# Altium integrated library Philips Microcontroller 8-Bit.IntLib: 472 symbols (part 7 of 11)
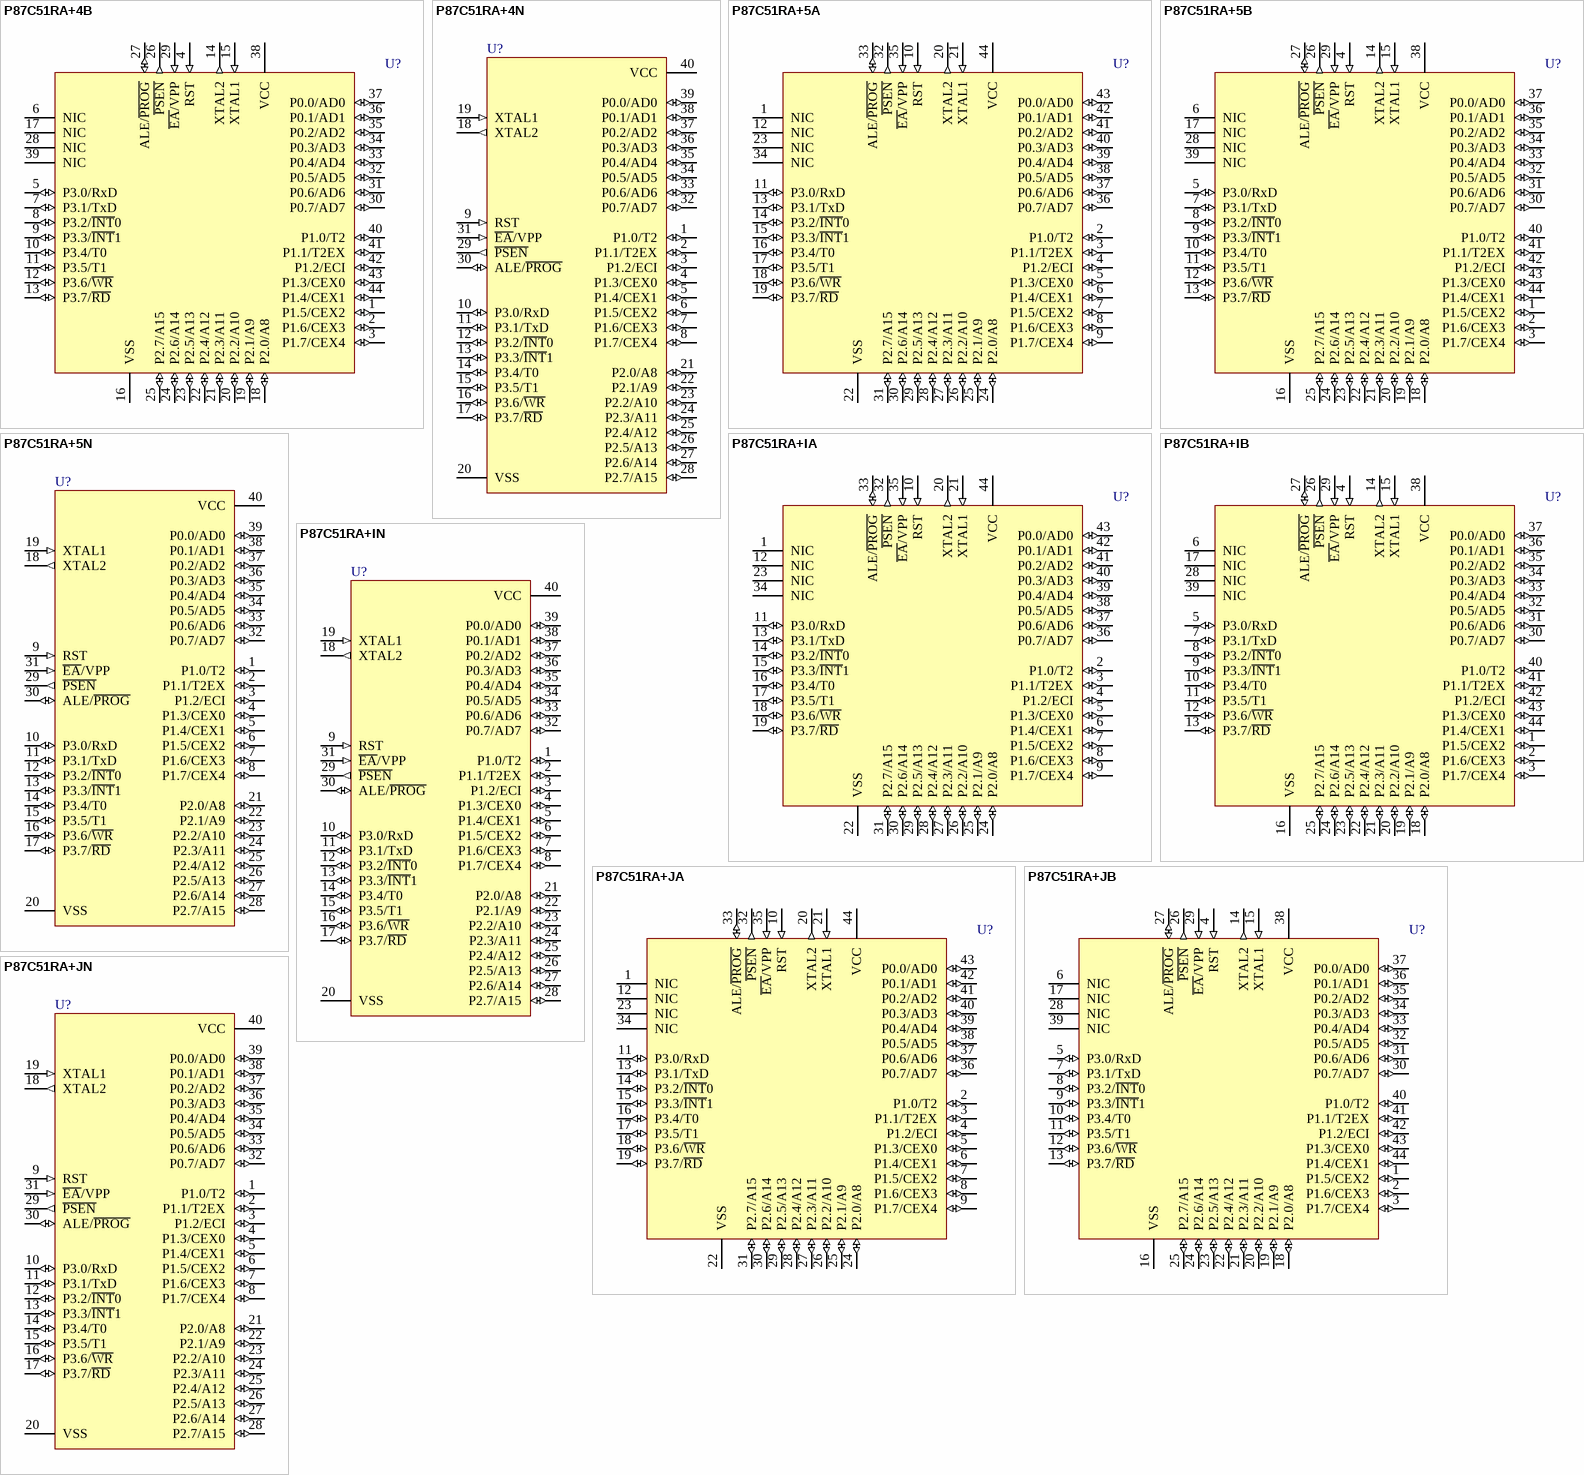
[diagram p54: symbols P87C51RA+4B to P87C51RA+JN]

## P87C51RA+5B
designator U?
80C51 8-Bit Microcontroller Family: 512 B RAM, 8 kB OTP, 2.7V-5.5V, Low Power, High Speed
footprint SOT307-2_N (QFP, 44-Leads, Body 10x10mm, Pitch 0.8mm, IPC Medium Density)
footprint SOT307-2_L (QFP, 44-Leads, Body 10x10mm, Pitch 0.8mm, IPC High Density)
footprint SOT307-2_M (QFP, 44-Leads, Body 10x10mm, Pitch 0.8mm, IPC Low Density)
pins: 1 P1.5/CEX2 (io), 2 P1.6/CEX3 (io), 3 P1.7/CEX4 (io), 4 RST (in), 5 P3.0/RxD (io), 6 NIC, 7 P3.1/TxD (io), 8 P3.2/~{INT}0 (io), 9 P3.3/~{INT}1 (io), 10 P3.4/T0 (io), 11 P3.5/T1 (io), 12 P3.6/~{WR} (io), 13 P3.7/~{RD} (io), 14 XTAL2 (out), 15 XTAL1 (in), 16 VSS (power), 17 NIC, 18 P2.0/A8 (io), 19 P2.1/A9 (io), 20 P2.2/A10 (io), 21 P2.3/A11 (io), 22 P2.4/A12 (io), 23 P2.5/A13 (io), 24 P2.6/A14 (io), 25 P2.7/A15 (io), 26 ~{PSEN} (out), 27 ALE/~{PROG} (io), 28 NIC, 29 ~{EA}/VPP (in), 30 P0.7/AD7 (io), 31 P0.6/AD6 (io), 32 P0.5/AD5 (io), 33 P0.4/AD4 (io), 34 P0.3/AD3 (io), 35 P0.2/AD2 (io), 36 P0.1/AD1 (io), 37 P0.0/AD0 (io), 38 VCC (power), 39 NIC, 40 P1.0/T2 (io), 41 P1.1/T2EX (io), 42 P1.2/ECI (io), 43 P1.3/CEX0 (io), 44 P1.4/CEX1 (io)

## P87C51RA+5N
designator U?
80C51 8-Bit Microcontroller Family: 512 B RAM, 8 kB OTP, 2.7V-5.5V, Low Power, High Speed
footprint SOT129-1 (DIP, Plastic; 40 Leads; Row Spacing 15.24 mm; Pitch 2.54 mm)
pins: 1 P1.0/T2 (io), 2 P1.1/T2EX (io), 3 P1.2/ECI (io), 4 P1.3/CEX0 (io), 5 P1.4/CEX1 (io), 6 P1.5/CEX2 (io), 7 P1.6/CEX3 (io), 8 P1.7/CEX4 (io), 9 RST (in), 10 P3.0/RxD (io), 11 P3.1/TxD (io), 12 P3.2/~{INT}0 (io), 13 P3.3/~{INT}1 (io), 14 P3.4/T0 (io), 15 P3.5/T1 (io), 16 P3.6/~{WR} (io), 17 P3.7/~{RD} (io), 18 XTAL2 (out), 19 XTAL1 (in), 20 VSS (power), 21 P2.0/A8 (io), 22 P2.1/A9 (io), 23 P2.2/A10 (io), 24 P2.3/A11 (io), 25 P2.4/A12 (io), 26 P2.5/A13 (io), 27 P2.6/A14 (io), 28 P2.7/A15 (io), 29 ~{PSEN} (out), 30 ALE/~{PROG} (io), 31 ~{EA}/VPP (in), 32 P0.7/AD7 (io), 33 P0.6/AD6 (io), 34 P0.5/AD5 (io), 35 P0.4/AD4 (io), 36 P0.3/AD3 (io), 37 P0.2/AD2 (io), 38 P0.1/AD1 (io), 39 P0.0/AD0 (io), 40 VCC (power)

## P87C51RA+IA
designator U?
80C51 8-Bit Microcontroller Family: 512 B RAM, 8 kB OTP, 5V, Low Power, High Speed
footprint SOT187-2_N (Leaded Chip Carrier, 44-Leads, Body 16.6x16.6mm, Pitch 1.27mm, IPC Medium Density)
footprint SOT187-2_L (Leaded Chip Carrier, 44-Leads, Body 16.6x16.6mm, Pitch 1.27mm, IPC High Density)
footprint SOT187-2_M (Leaded Chip Carrier, 44-Leads, Body 16.6x16.6mm, Pitch 1.27mm, IPC Low Density)
pins: 1 NIC, 2 P1.0/T2 (io), 3 P1.1/T2EX (io), 4 P1.2/ECI (io), 5 P1.3/CEX0 (io), 6 P1.4/CEX1 (io), 7 P1.5/CEX2 (io), 8 P1.6/CEX3 (io), 9 P1.7/CEX4 (io), 10 RST (in), 11 P3.0/RxD (io), 12 NIC, 13 P3.1/TxD (io), 14 P3.2/~{INT}0 (io), 15 P3.3/~{INT}1 (io), 16 P3.4/T0 (io), 17 P3.5/T1 (io), 18 P3.6/~{WR} (io), 19 P3.7/~{RD} (io), 20 XTAL2 (out), 21 XTAL1 (in), 22 VSS (power), 23 NIC, 24 P2.0/A8 (io), 25 P2.1/A9 (io), 26 P2.2/A10 (io), 27 P2.3/A11 (io), 28 P2.4/A12 (io), 29 P2.5/A13 (io), 30 P2.6/A14 (io), 31 P2.7/A15 (io), 32 ~{PSEN} (out), 33 ALE/~{PROG} (io), 34 NIC, 35 ~{EA}/VPP (in), 36 P0.7/AD7 (io), 37 P0.6/AD6 (io), 38 P0.5/AD5 (io), 39 P0.4/AD4 (io), 40 P0.3/AD3 (io), 41 P0.2/AD2 (io), 42 P0.1/AD1 (io), 43 P0.0/AD0 (io), 44 VCC (power)

## P87C51RA+IB
designator U?
80C51 8-Bit Microcontroller Family: 512 B RAM, 8 kB OTP, 5V, Low Power, High Speed
footprint SOT307-2_N (QFP, 44-Leads, Body 10x10mm, Pitch 0.8mm, IPC Medium Density)
footprint SOT307-2_L (QFP, 44-Leads, Body 10x10mm, Pitch 0.8mm, IPC High Density)
footprint SOT307-2_M (QFP, 44-Leads, Body 10x10mm, Pitch 0.8mm, IPC Low Density)
pins: 1 P1.5/CEX2 (io), 2 P1.6/CEX3 (io), 3 P1.7/CEX4 (io), 4 RST (in), 5 P3.0/RxD (io), 6 NIC, 7 P3.1/TxD (io), 8 P3.2/~{INT}0 (io), 9 P3.3/~{INT}1 (io), 10 P3.4/T0 (io), 11 P3.5/T1 (io), 12 P3.6/~{WR} (io), 13 P3.7/~{RD} (io), 14 XTAL2 (out), 15 XTAL1 (in), 16 VSS (power), 17 NIC, 18 P2.0/A8 (io), 19 P2.1/A9 (io), 20 P2.2/A10 (io), 21 P2.3/A11 (io), 22 P2.4/A12 (io), 23 P2.5/A13 (io), 24 P2.6/A14 (io), 25 P2.7/A15 (io), 26 ~{PSEN} (out), 27 ALE/~{PROG} (io), 28 NIC, 29 ~{EA}/VPP (in), 30 P0.7/AD7 (io), 31 P0.6/AD6 (io), 32 P0.5/AD5 (io), 33 P0.4/AD4 (io), 34 P0.3/AD3 (io), 35 P0.2/AD2 (io), 36 P0.1/AD1 (io), 37 P0.0/AD0 (io), 38 VCC (power), 39 NIC, 40 P1.0/T2 (io), 41 P1.1/T2EX (io), 42 P1.2/ECI (io), 43 P1.3/CEX0 (io), 44 P1.4/CEX1 (io)

## P87C51RA+IN
designator U?
80C51 8-Bit Microcontroller Family: 512 B RAM, 8 kB OTP, 5V, Low Power, High Speed
footprint SOT129-1 (DIP, Plastic; 40 Leads; Row Spacing 15.24 mm; Pitch 2.54 mm)
pins: 1 P1.0/T2 (io), 2 P1.1/T2EX (io), 3 P1.2/ECI (io), 4 P1.3/CEX0 (io), 5 P1.4/CEX1 (io), 6 P1.5/CEX2 (io), 7 P1.6/CEX3 (io), 8 P1.7/CEX4 (io), 9 RST (in), 10 P3.0/RxD (io), 11 P3.1/TxD (io), 12 P3.2/~{INT}0 (io), 13 P3.3/~{INT}1 (io), 14 P3.4/T0 (io), 15 P3.5/T1 (io), 16 P3.6/~{WR} (io), 17 P3.7/~{RD} (io), 18 XTAL2 (out), 19 XTAL1 (in), 20 VSS (power), 21 P2.0/A8 (io), 22 P2.1/A9 (io), 23 P2.2/A10 (io), 24 P2.3/A11 (io), 25 P2.4/A12 (io), 26 P2.5/A13 (io), 27 P2.6/A14 (io), 28 P2.7/A15 (io), 29 ~{PSEN} (out), 30 ALE/~{PROG} (io), 31 ~{EA}/VPP (in), 32 P0.7/AD7 (io), 33 P0.6/AD6 (io), 34 P0.5/AD5 (io), 35 P0.4/AD4 (io), 36 P0.3/AD3 (io), 37 P0.2/AD2 (io), 38 P0.1/AD1 (io), 39 P0.0/AD0 (io), 40 VCC (power)

## P87C51RA+JA
designator U?
80C51 8-Bit Microcontroller Family: 512 B RAM, 8 kB OTP, 5V, Low Power, High Speed
footprint SOT187-2_N (Leaded Chip Carrier, 44-Leads, Body 16.6x16.6mm, Pitch 1.27mm, IPC Medium Density)
footprint SOT187-2_L (Leaded Chip Carrier, 44-Leads, Body 16.6x16.6mm, Pitch 1.27mm, IPC High Density)
footprint SOT187-2_M (Leaded Chip Carrier, 44-Leads, Body 16.6x16.6mm, Pitch 1.27mm, IPC Low Density)
pins: 1 NIC, 2 P1.0/T2 (io), 3 P1.1/T2EX (io), 4 P1.2/ECI (io), 5 P1.3/CEX0 (io), 6 P1.4/CEX1 (io), 7 P1.5/CEX2 (io), 8 P1.6/CEX3 (io), 9 P1.7/CEX4 (io), 10 RST (in), 11 P3.0/RxD (io), 12 NIC, 13 P3.1/TxD (io), 14 P3.2/~{INT}0 (io), 15 P3.3/~{INT}1 (io), 16 P3.4/T0 (io), 17 P3.5/T1 (io), 18 P3.6/~{WR} (io), 19 P3.7/~{RD} (io), 20 XTAL2 (out), 21 XTAL1 (in), 22 VSS (power), 23 NIC, 24 P2.0/A8 (io), 25 P2.1/A9 (io), 26 P2.2/A10 (io), 27 P2.3/A11 (io), 28 P2.4/A12 (io), 29 P2.5/A13 (io), 30 P2.6/A14 (io), 31 P2.7/A15 (io), 32 ~{PSEN} (out), 33 ALE/~{PROG} (io), 34 NIC, 35 ~{EA}/VPP (in), 36 P0.7/AD7 (io), 37 P0.6/AD6 (io), 38 P0.5/AD5 (io), 39 P0.4/AD4 (io), 40 P0.3/AD3 (io), 41 P0.2/AD2 (io), 42 P0.1/AD1 (io), 43 P0.0/AD0 (io), 44 VCC (power)

## P87C51RA+JB
designator U?
80C51 8-Bit Microcontroller Family: 512 B RAM, 8 kB OTP, 5V, Low Power, High Speed
footprint SOT307-2_N (QFP, 44-Leads, Body 10x10mm, Pitch 0.8mm, IPC Medium Density)
footprint SOT307-2_L (QFP, 44-Leads, Body 10x10mm, Pitch 0.8mm, IPC High Density)
footprint SOT307-2_M (QFP, 44-Leads, Body 10x10mm, Pitch 0.8mm, IPC Low Density)
pins: 1 P1.5/CEX2 (io), 2 P1.6/CEX3 (io), 3 P1.7/CEX4 (io), 4 RST (in), 5 P3.0/RxD (io), 6 NIC, 7 P3.1/TxD (io), 8 P3.2/~{INT}0 (io), 9 P3.3/~{INT}1 (io), 10 P3.4/T0 (io), 11 P3.5/T1 (io), 12 P3.6/~{WR} (io), 13 P3.7/~{RD} (io), 14 XTAL2 (out), 15 XTAL1 (in), 16 VSS (power), 17 NIC, 18 P2.0/A8 (io), 19 P2.1/A9 (io), 20 P2.2/A10 (io), 21 P2.3/A11 (io), 22 P2.4/A12 (io), 23 P2.5/A13 (io), 24 P2.6/A14 (io), 25 P2.7/A15 (io), 26 ~{PSEN} (out), 27 ALE/~{PROG} (io), 28 NIC, 29 ~{EA}/VPP (in), 30 P0.7/AD7 (io), 31 P0.6/AD6 (io), 32 P0.5/AD5 (io), 33 P0.4/AD4 (io), 34 P0.3/AD3 (io), 35 P0.2/AD2 (io), 36 P0.1/AD1 (io), 37 P0.0/AD0 (io), 38 VCC (power), 39 NIC, 40 P1.0/T2 (io), 41 P1.1/T2EX (io), 42 P1.2/ECI (io), 43 P1.3/CEX0 (io), 44 P1.4/CEX1 (io)

## P87C51RA+JN
designator U?
80C51 8-Bit Microcontroller Family: 512 B RAM, 8 kB OTP, 5V, Low Power, High Speed
footprint SOT129-1 (DIP, Plastic; 40 Leads; Row Spacing 15.24 mm; Pitch 2.54 mm)
pins: 1 P1.0/T2 (io), 2 P1.1/T2EX (io), 3 P1.2/ECI (io), 4 P1.3/CEX0 (io), 5 P1.4/CEX1 (io), 6 P1.5/CEX2 (io), 7 P1.6/CEX3 (io), 8 P1.7/CEX4 (io), 9 RST (in), 10 P3.0/RxD (io), 11 P3.1/TxD (io), 12 P3.2/~{INT}0 (io), 13 P3.3/~{INT}1 (io), 14 P3.4/T0 (io), 15 P3.5/T1 (io), 16 P3.6/~{WR} (io), 17 P3.7/~{RD} (io), 18 XTAL2 (out), 19 XTAL1 (in), 20 VSS (power), 21 P2.0/A8 (io), 22 P2.1/A9 (io), 23 P2.2/A10 (io), 24 P2.3/A11 (io), 25 P2.4/A12 (io), 26 P2.5/A13 (io), 27 P2.6/A14 (io), 28 P2.7/A15 (io), 29 ~{PSEN} (out), 30 ALE/~{PROG} (io), 31 ~{EA}/VPP (in), 32 P0.7/AD7 (io), 33 P0.6/AD6 (io), 34 P0.5/AD5 (io), 35 P0.4/AD4 (io), 36 P0.3/AD3 (io), 37 P0.2/AD2 (io), 38 P0.1/AD1 (io), 39 P0.0/AD0 (io), 40 VCC (power)

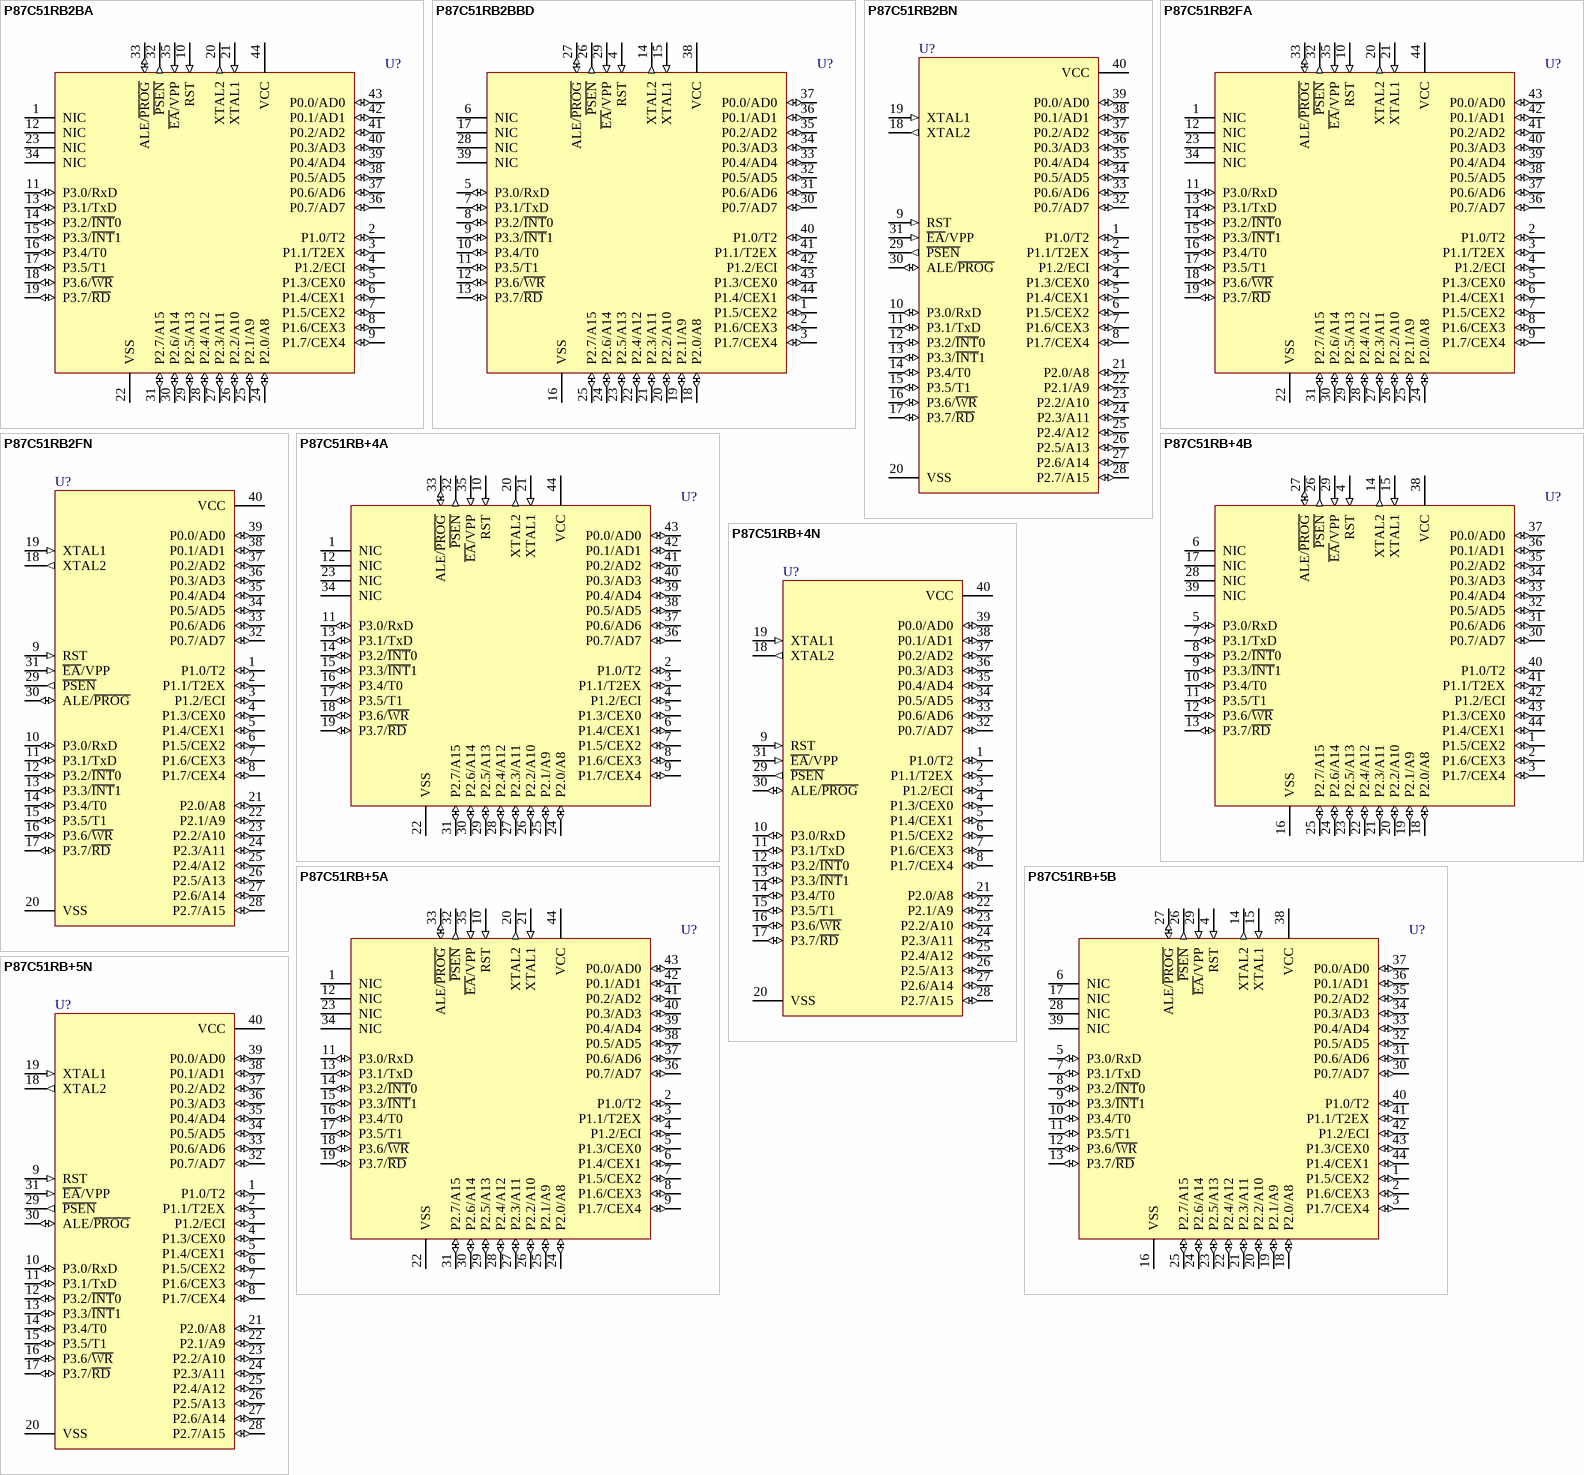
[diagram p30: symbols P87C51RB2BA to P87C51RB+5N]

## P87C51RB2BA
designator U?
80C51 8-Bit Microcontroller Family: 16 kB OTP with 512 B RAM, 2.7 to 5.5 V, Low Power, High Speed
footprint SOT187-2_N (Leaded Chip Carrier, 44-Leads, Body 16.6x16.6mm, Pitch 1.27mm, IPC Medium Density)
footprint SOT187-2_L (Leaded Chip Carrier, 44-Leads, Body 16.6x16.6mm, Pitch 1.27mm, IPC High Density)
footprint SOT187-2_M (Leaded Chip Carrier, 44-Leads, Body 16.6x16.6mm, Pitch 1.27mm, IPC Low Density)
pins: 1 NIC, 2 P1.0/T2 (io), 3 P1.1/T2EX (io), 4 P1.2/ECI (io), 5 P1.3/CEX0 (io), 6 P1.4/CEX1 (io), 7 P1.5/CEX2 (io), 8 P1.6/CEX3 (io), 9 P1.7/CEX4 (io), 10 RST (in), 11 P3.0/RxD (io), 12 NIC, 13 P3.1/TxD (io), 14 P3.2/~{INT}0 (io), 15 P3.3/~{INT}1 (io), 16 P3.4/T0 (io), 17 P3.5/T1 (io), 18 P3.6/~{WR} (io), 19 P3.7/~{RD} (io), 20 XTAL2 (out), 21 XTAL1 (in), 22 VSS (power), 23 NIC, 24 P2.0/A8 (io), 25 P2.1/A9 (io), 26 P2.2/A10 (io), 27 P2.3/A11 (io), 28 P2.4/A12 (io), 29 P2.5/A13 (io), 30 P2.6/A14 (io), 31 P2.7/A15 (io), 32 ~{PSEN} (out), 33 ALE/~{PROG} (io), 34 NIC, 35 ~{EA}/VPP (in), 36 P0.7/AD7 (io), 37 P0.6/AD6 (io), 38 P0.5/AD5 (io), 39 P0.4/AD4 (io), 40 P0.3/AD3 (io), 41 P0.2/AD2 (io), 42 P0.1/AD1 (io), 43 P0.0/AD0 (io), 44 VCC (power)

## P87C51RB2BBD
designator U?
80C51 8-Bit Microcontroller Family: 16 kB OTP with 512 B RAM, 2.7 to 5.5 V, Low Power, High Speed
footprint SOT389-1_N (Thin QFP, 44-Leads, Body 10x10mm, Pitch 0.8mm, IPC Medium Density)
footprint SOT389-1_L (Thin QFP, 44-Leads, Body 10x10mm, Pitch 0.8mm, IPC High Density)
footprint SOT389-1_M (Thin QFP, 44-Leads, Body 10x10mm, Pitch 0.8mm, IPC Low Density)
pins: 1 P1.5/CEX2 (io), 2 P1.6/CEX3 (io), 3 P1.7/CEX4 (io), 4 RST (in), 5 P3.0/RxD (io), 6 NIC, 7 P3.1/TxD (io), 8 P3.2/~{INT}0 (io), 9 P3.3/~{INT}1 (io), 10 P3.4/T0 (io), 11 P3.5/T1 (io), 12 P3.6/~{WR} (io), 13 P3.7/~{RD} (io), 14 XTAL2 (out), 15 XTAL1 (in), 16 VSS (power), 17 NIC, 18 P2.0/A8 (io), 19 P2.1/A9 (io), 20 P2.2/A10 (io), 21 P2.3/A11 (io), 22 P2.4/A12 (io), 23 P2.5/A13 (io), 24 P2.6/A14 (io), 25 P2.7/A15 (io), 26 ~{PSEN} (out), 27 ALE/~{PROG} (io), 28 NIC, 29 ~{EA}/VPP (in), 30 P0.7/AD7 (io), 31 P0.6/AD6 (io), 32 P0.5/AD5 (io), 33 P0.4/AD4 (io), 34 P0.3/AD3 (io), 35 P0.2/AD2 (io), 36 P0.1/AD1 (io), 37 P0.0/AD0 (io), 38 VCC (power), 39 NIC, 40 P1.0/T2 (io), 41 P1.1/T2EX (io), 42 P1.2/ECI (io), 43 P1.3/CEX0 (io), 44 P1.4/CEX1 (io)

## P87C51RB2BN
designator U?
80C51 8-Bit Microcontroller Family: 16 kB OTP with 512 B RAM, 2.7 to 5.5 V, Low Power, High Speed
footprint SOT129-1 (DIP, Plastic; 40 Leads; Row Spacing 15.24 mm; Pitch 2.54 mm)
pins: 1 P1.0/T2 (io), 2 P1.1/T2EX (io), 3 P1.2/ECI (io), 4 P1.3/CEX0 (io), 5 P1.4/CEX1 (io), 6 P1.5/CEX2 (io), 7 P1.6/CEX3 (io), 8 P1.7/CEX4 (io), 9 RST (in), 10 P3.0/RxD (io), 11 P3.1/TxD (io), 12 P3.2/~{INT}0 (io), 13 P3.3/~{INT}1 (io), 14 P3.4/T0 (io), 15 P3.5/T1 (io), 16 P3.6/~{WR} (io), 17 P3.7/~{RD} (io), 18 XTAL2 (out), 19 XTAL1 (in), 20 VSS (power), 21 P2.0/A8 (io), 22 P2.1/A9 (io), 23 P2.2/A10 (io), 24 P2.3/A11 (io), 25 P2.4/A12 (io), 26 P2.5/A13 (io), 27 P2.6/A14 (io), 28 P2.7/A15 (io), 29 ~{PSEN} (out), 30 ALE/~{PROG} (io), 31 ~{EA}/VPP (in), 32 P0.7/AD7 (io), 33 P0.6/AD6 (io), 34 P0.5/AD5 (io), 35 P0.4/AD4 (io), 36 P0.3/AD3 (io), 37 P0.2/AD2 (io), 38 P0.1/AD1 (io), 39 P0.0/AD0 (io), 40 VCC (power)

## P87C51RB2FA
designator U?
80C51 8-Bit Microcontroller Family: 16 kB OTP with 512 B RAM, 2.7 to 5.5 V, Low Power, High Speed
footprint SOT187-2_N (Leaded Chip Carrier, 44-Leads, Body 16.6x16.6mm, Pitch 1.27mm, IPC Medium Density)
footprint SOT187-2_L (Leaded Chip Carrier, 44-Leads, Body 16.6x16.6mm, Pitch 1.27mm, IPC High Density)
footprint SOT187-2_M (Leaded Chip Carrier, 44-Leads, Body 16.6x16.6mm, Pitch 1.27mm, IPC Low Density)
pins: 1 NIC, 2 P1.0/T2 (io), 3 P1.1/T2EX (io), 4 P1.2/ECI (io), 5 P1.3/CEX0 (io), 6 P1.4/CEX1 (io), 7 P1.5/CEX2 (io), 8 P1.6/CEX3 (io), 9 P1.7/CEX4 (io), 10 RST (in), 11 P3.0/RxD (io), 12 NIC, 13 P3.1/TxD (io), 14 P3.2/~{INT}0 (io), 15 P3.3/~{INT}1 (io), 16 P3.4/T0 (io), 17 P3.5/T1 (io), 18 P3.6/~{WR} (io), 19 P3.7/~{RD} (io), 20 XTAL2 (out), 21 XTAL1 (in), 22 VSS (power), 23 NIC, 24 P2.0/A8 (io), 25 P2.1/A9 (io), 26 P2.2/A10 (io), 27 P2.3/A11 (io), 28 P2.4/A12 (io), 29 P2.5/A13 (io), 30 P2.6/A14 (io), 31 P2.7/A15 (io), 32 ~{PSEN} (out), 33 ALE/~{PROG} (io), 34 NIC, 35 ~{EA}/VPP (in), 36 P0.7/AD7 (io), 37 P0.6/AD6 (io), 38 P0.5/AD5 (io), 39 P0.4/AD4 (io), 40 P0.3/AD3 (io), 41 P0.2/AD2 (io), 42 P0.1/AD1 (io), 43 P0.0/AD0 (io), 44 VCC (power)

## P87C51RB2FN
designator U?
80C51 8-Bit Microcontroller Family: 16 kB OTP with 512 B RAM, 2.7 to 5.5 V, Low Power, High Speed
footprint SOT129-1 (DIP, Plastic; 40 Leads; Row Spacing 15.24 mm; Pitch 2.54 mm)
pins: 1 P1.0/T2 (io), 2 P1.1/T2EX (io), 3 P1.2/ECI (io), 4 P1.3/CEX0 (io), 5 P1.4/CEX1 (io), 6 P1.5/CEX2 (io), 7 P1.6/CEX3 (io), 8 P1.7/CEX4 (io), 9 RST (in), 10 P3.0/RxD (io), 11 P3.1/TxD (io), 12 P3.2/~{INT}0 (io), 13 P3.3/~{INT}1 (io), 14 P3.4/T0 (io), 15 P3.5/T1 (io), 16 P3.6/~{WR} (io), 17 P3.7/~{RD} (io), 18 XTAL2 (out), 19 XTAL1 (in), 20 VSS (power), 21 P2.0/A8 (io), 22 P2.1/A9 (io), 23 P2.2/A10 (io), 24 P2.3/A11 (io), 25 P2.4/A12 (io), 26 P2.5/A13 (io), 27 P2.6/A14 (io), 28 P2.7/A15 (io), 29 ~{PSEN} (out), 30 ALE/~{PROG} (io), 31 ~{EA}/VPP (in), 32 P0.7/AD7 (io), 33 P0.6/AD6 (io), 34 P0.5/AD5 (io), 35 P0.4/AD4 (io), 36 P0.3/AD3 (io), 37 P0.2/AD2 (io), 38 P0.1/AD1 (io), 39 P0.0/AD0 (io), 40 VCC (power)

## P87C51RB+4A
designator U?
80C51 8-Bit Microcontroller Family: 512 B RAM, 16 kB OTP, 2.7V-5.5V, Low Power, High Speed
footprint SOT187-2_N (Leaded Chip Carrier, 44-Leads, Body 16.6x16.6mm, Pitch 1.27mm, IPC Medium Density)
footprint SOT187-2_L (Leaded Chip Carrier, 44-Leads, Body 16.6x16.6mm, Pitch 1.27mm, IPC High Density)
footprint SOT187-2_M (Leaded Chip Carrier, 44-Leads, Body 16.6x16.6mm, Pitch 1.27mm, IPC Low Density)
pins: 1 NIC, 2 P1.0/T2 (io), 3 P1.1/T2EX (io), 4 P1.2/ECI (io), 5 P1.3/CEX0 (io), 6 P1.4/CEX1 (io), 7 P1.5/CEX2 (io), 8 P1.6/CEX3 (io), 9 P1.7/CEX4 (io), 10 RST (in), 11 P3.0/RxD (io), 12 NIC, 13 P3.1/TxD (io), 14 P3.2/~{INT}0 (io), 15 P3.3/~{INT}1 (io), 16 P3.4/T0 (io), 17 P3.5/T1 (io), 18 P3.6/~{WR} (io), 19 P3.7/~{RD} (io), 20 XTAL2 (out), 21 XTAL1 (in), 22 VSS (power), 23 NIC, 24 P2.0/A8 (io), 25 P2.1/A9 (io), 26 P2.2/A10 (io), 27 P2.3/A11 (io), 28 P2.4/A12 (io), 29 P2.5/A13 (io), 30 P2.6/A14 (io), 31 P2.7/A15 (io), 32 ~{PSEN} (out), 33 ALE/~{PROG} (io), 34 NIC, 35 ~{EA}/VPP (in), 36 P0.7/AD7 (io), 37 P0.6/AD6 (io), 38 P0.5/AD5 (io), 39 P0.4/AD4 (io), 40 P0.3/AD3 (io), 41 P0.2/AD2 (io), 42 P0.1/AD1 (io), 43 P0.0/AD0 (io), 44 VCC (power)

## P87C51RB+4B
designator U?
80C51 8-Bit Microcontroller Family: 512 B RAM, 16 kB OTP, 2.7V-5.5V, Low Power, High Speed
footprint SOT307-2_N (QFP, 44-Leads, Body 10x10mm, Pitch 0.8mm, IPC Medium Density)
footprint SOT307-2_L (QFP, 44-Leads, Body 10x10mm, Pitch 0.8mm, IPC High Density)
footprint SOT307-2_M (QFP, 44-Leads, Body 10x10mm, Pitch 0.8mm, IPC Low Density)
pins: 1 P1.5/CEX2 (io), 2 P1.6/CEX3 (io), 3 P1.7/CEX4 (io), 4 RST (in), 5 P3.0/RxD (io), 6 NIC, 7 P3.1/TxD (io), 8 P3.2/~{INT}0 (io), 9 P3.3/~{INT}1 (io), 10 P3.4/T0 (io), 11 P3.5/T1 (io), 12 P3.6/~{WR} (io), 13 P3.7/~{RD} (io), 14 XTAL2 (out), 15 XTAL1 (in), 16 VSS (power), 17 NIC, 18 P2.0/A8 (io), 19 P2.1/A9 (io), 20 P2.2/A10 (io), 21 P2.3/A11 (io), 22 P2.4/A12 (io), 23 P2.5/A13 (io), 24 P2.6/A14 (io), 25 P2.7/A15 (io), 26 ~{PSEN} (out), 27 ALE/~{PROG} (io), 28 NIC, 29 ~{EA}/VPP (in), 30 P0.7/AD7 (io), 31 P0.6/AD6 (io), 32 P0.5/AD5 (io), 33 P0.4/AD4 (io), 34 P0.3/AD3 (io), 35 P0.2/AD2 (io), 36 P0.1/AD1 (io), 37 P0.0/AD0 (io), 38 VCC (power), 39 NIC, 40 P1.0/T2 (io), 41 P1.1/T2EX (io), 42 P1.2/ECI (io), 43 P1.3/CEX0 (io), 44 P1.4/CEX1 (io)

## P87C51RB+4N
designator U?
80C51 8-Bit Microcontroller Family: 512 B RAM, 16 kB OTP, 2.7V-5.5V, Low Power, High Speed
footprint SOT129-1 (DIP, Plastic; 40 Leads; Row Spacing 15.24 mm; Pitch 2.54 mm)
pins: 1 P1.0/T2 (io), 2 P1.1/T2EX (io), 3 P1.2/ECI (io), 4 P1.3/CEX0 (io), 5 P1.4/CEX1 (io), 6 P1.5/CEX2 (io), 7 P1.6/CEX3 (io), 8 P1.7/CEX4 (io), 9 RST (in), 10 P3.0/RxD (io), 11 P3.1/TxD (io), 12 P3.2/~{INT}0 (io), 13 P3.3/~{INT}1 (io), 14 P3.4/T0 (io), 15 P3.5/T1 (io), 16 P3.6/~{WR} (io), 17 P3.7/~{RD} (io), 18 XTAL2 (out), 19 XTAL1 (in), 20 VSS (power), 21 P2.0/A8 (io), 22 P2.1/A9 (io), 23 P2.2/A10 (io), 24 P2.3/A11 (io), 25 P2.4/A12 (io), 26 P2.5/A13 (io), 27 P2.6/A14 (io), 28 P2.7/A15 (io), 29 ~{PSEN} (out), 30 ALE/~{PROG} (io), 31 ~{EA}/VPP (in), 32 P0.7/AD7 (io), 33 P0.6/AD6 (io), 34 P0.5/AD5 (io), 35 P0.4/AD4 (io), 36 P0.3/AD3 (io), 37 P0.2/AD2 (io), 38 P0.1/AD1 (io), 39 P0.0/AD0 (io), 40 VCC (power)

## P87C51RB+5A
designator U?
80C51 8-Bit Microcontroller Family: 512 B RAM, 16 kB OTP, 2.7V-5.5V, Low Power, High Speed
footprint SOT187-2_N (Leaded Chip Carrier, 44-Leads, Body 16.6x16.6mm, Pitch 1.27mm, IPC Medium Density)
footprint SOT187-2_L (Leaded Chip Carrier, 44-Leads, Body 16.6x16.6mm, Pitch 1.27mm, IPC High Density)
footprint SOT187-2_M (Leaded Chip Carrier, 44-Leads, Body 16.6x16.6mm, Pitch 1.27mm, IPC Low Density)
pins: 1 NIC, 2 P1.0/T2 (io), 3 P1.1/T2EX (io), 4 P1.2/ECI (io), 5 P1.3/CEX0 (io), 6 P1.4/CEX1 (io), 7 P1.5/CEX2 (io), 8 P1.6/CEX3 (io), 9 P1.7/CEX4 (io), 10 RST (in), 11 P3.0/RxD (io), 12 NIC, 13 P3.1/TxD (io), 14 P3.2/~{INT}0 (io), 15 P3.3/~{INT}1 (io), 16 P3.4/T0 (io), 17 P3.5/T1 (io), 18 P3.6/~{WR} (io), 19 P3.7/~{RD} (io), 20 XTAL2 (out), 21 XTAL1 (in), 22 VSS (power), 23 NIC, 24 P2.0/A8 (io), 25 P2.1/A9 (io), 26 P2.2/A10 (io), 27 P2.3/A11 (io), 28 P2.4/A12 (io), 29 P2.5/A13 (io), 30 P2.6/A14 (io), 31 P2.7/A15 (io), 32 ~{PSEN} (out), 33 ALE/~{PROG} (io), 34 NIC, 35 ~{EA}/VPP (in), 36 P0.7/AD7 (io), 37 P0.6/AD6 (io), 38 P0.5/AD5 (io), 39 P0.4/AD4 (io), 40 P0.3/AD3 (io), 41 P0.2/AD2 (io), 42 P0.1/AD1 (io), 43 P0.0/AD0 (io), 44 VCC (power)

## P87C51RB+5B
designator U?
80C51 8-Bit Microcontroller Family: 512 B RAM, 16 kB OTP, 2.7V-5.5V, Low Power, High Speed
footprint SOT307-2_N (QFP, 44-Leads, Body 10x10mm, Pitch 0.8mm, IPC Medium Density)
footprint SOT307-2_L (QFP, 44-Leads, Body 10x10mm, Pitch 0.8mm, IPC High Density)
footprint SOT307-2_M (QFP, 44-Leads, Body 10x10mm, Pitch 0.8mm, IPC Low Density)
pins: 1 P1.5/CEX2 (io), 2 P1.6/CEX3 (io), 3 P1.7/CEX4 (io), 4 RST (in), 5 P3.0/RxD (io), 6 NIC, 7 P3.1/TxD (io), 8 P3.2/~{INT}0 (io), 9 P3.3/~{INT}1 (io), 10 P3.4/T0 (io), 11 P3.5/T1 (io), 12 P3.6/~{WR} (io), 13 P3.7/~{RD} (io), 14 XTAL2 (out), 15 XTAL1 (in), 16 VSS (power), 17 NIC, 18 P2.0/A8 (io), 19 P2.1/A9 (io), 20 P2.2/A10 (io), 21 P2.3/A11 (io), 22 P2.4/A12 (io), 23 P2.5/A13 (io), 24 P2.6/A14 (io), 25 P2.7/A15 (io), 26 ~{PSEN} (out), 27 ALE/~{PROG} (io), 28 NIC, 29 ~{EA}/VPP (in), 30 P0.7/AD7 (io), 31 P0.6/AD6 (io), 32 P0.5/AD5 (io), 33 P0.4/AD4 (io), 34 P0.3/AD3 (io), 35 P0.2/AD2 (io), 36 P0.1/AD1 (io), 37 P0.0/AD0 (io), 38 VCC (power), 39 NIC, 40 P1.0/T2 (io), 41 P1.1/T2EX (io), 42 P1.2/ECI (io), 43 P1.3/CEX0 (io), 44 P1.4/CEX1 (io)

## P87C51RB+5N
designator U?
80C51 8-Bit Microcontroller Family: 512 B RAM, 16 kB OTP, 2.7V-5.5V, Low Power, High Speed
footprint SOT129-1 (DIP, Plastic; 40 Leads; Row Spacing 15.24 mm; Pitch 2.54 mm)
pins: 1 P1.0/T2 (io), 2 P1.1/T2EX (io), 3 P1.2/ECI (io), 4 P1.3/CEX0 (io), 5 P1.4/CEX1 (io), 6 P1.5/CEX2 (io), 7 P1.6/CEX3 (io), 8 P1.7/CEX4 (io), 9 RST (in), 10 P3.0/RxD (io), 11 P3.1/TxD (io), 12 P3.2/~{INT}0 (io), 13 P3.3/~{INT}1 (io), 14 P3.4/T0 (io), 15 P3.5/T1 (io), 16 P3.6/~{WR} (io), 17 P3.7/~{RD} (io), 18 XTAL2 (out), 19 XTAL1 (in), 20 VSS (power), 21 P2.0/A8 (io), 22 P2.1/A9 (io), 23 P2.2/A10 (io), 24 P2.3/A11 (io), 25 P2.4/A12 (io), 26 P2.5/A13 (io), 27 P2.6/A14 (io), 28 P2.7/A15 (io), 29 ~{PSEN} (out), 30 ALE/~{PROG} (io), 31 ~{EA}/VPP (in), 32 P0.7/AD7 (io), 33 P0.6/AD6 (io), 34 P0.5/AD5 (io), 35 P0.4/AD4 (io), 36 P0.3/AD3 (io), 37 P0.2/AD2 (io), 38 P0.1/AD1 (io), 39 P0.0/AD0 (io), 40 VCC (power)

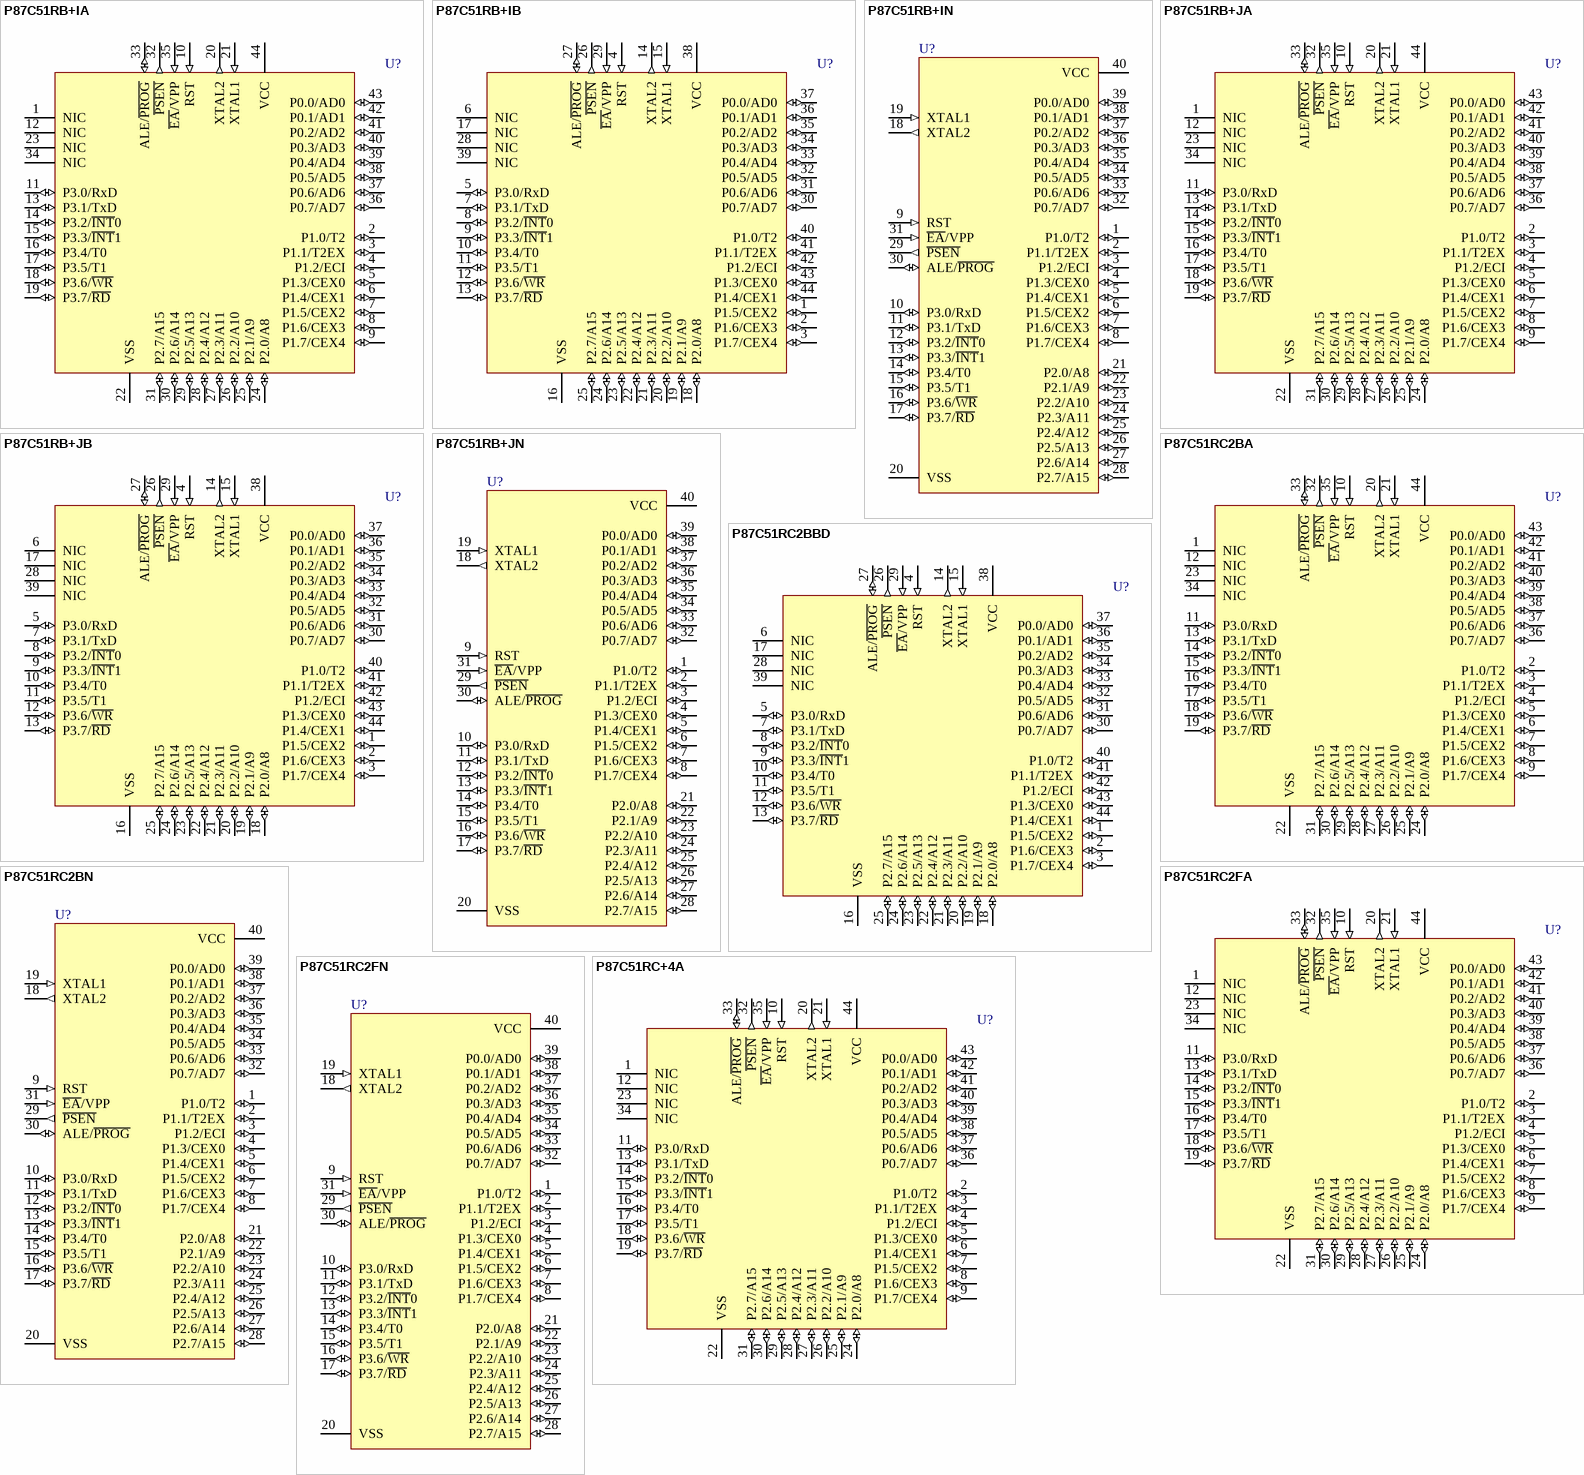
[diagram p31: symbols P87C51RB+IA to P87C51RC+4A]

## P87C51RB+IA
designator U?
80C51 8-Bit Microcontroller Family: 512 B RAM, 16 kB OTP, 5V, Low Power, High Speed
footprint SOT187-2_N (Leaded Chip Carrier, 44-Leads, Body 16.6x16.6mm, Pitch 1.27mm, IPC Medium Density)
footprint SOT187-2_L (Leaded Chip Carrier, 44-Leads, Body 16.6x16.6mm, Pitch 1.27mm, IPC High Density)
footprint SOT187-2_M (Leaded Chip Carrier, 44-Leads, Body 16.6x16.6mm, Pitch 1.27mm, IPC Low Density)
pins: 1 NIC, 2 P1.0/T2 (io), 3 P1.1/T2EX (io), 4 P1.2/ECI (io), 5 P1.3/CEX0 (io), 6 P1.4/CEX1 (io), 7 P1.5/CEX2 (io), 8 P1.6/CEX3 (io), 9 P1.7/CEX4 (io), 10 RST (in), 11 P3.0/RxD (io), 12 NIC, 13 P3.1/TxD (io), 14 P3.2/~{INT}0 (io), 15 P3.3/~{INT}1 (io), 16 P3.4/T0 (io), 17 P3.5/T1 (io), 18 P3.6/~{WR} (io), 19 P3.7/~{RD} (io), 20 XTAL2 (out), 21 XTAL1 (in), 22 VSS (power), 23 NIC, 24 P2.0/A8 (io), 25 P2.1/A9 (io), 26 P2.2/A10 (io), 27 P2.3/A11 (io), 28 P2.4/A12 (io), 29 P2.5/A13 (io), 30 P2.6/A14 (io), 31 P2.7/A15 (io), 32 ~{PSEN} (out), 33 ALE/~{PROG} (io), 34 NIC, 35 ~{EA}/VPP (in), 36 P0.7/AD7 (io), 37 P0.6/AD6 (io), 38 P0.5/AD5 (io), 39 P0.4/AD4 (io), 40 P0.3/AD3 (io), 41 P0.2/AD2 (io), 42 P0.1/AD1 (io), 43 P0.0/AD0 (io), 44 VCC (power)

## P87C51RB+IB
designator U?
80C51 8-Bit Microcontroller Family: 512 B RAM, 16 kB OTP, 5V, Low Power, High Speed
footprint SOT307-2_N (QFP, 44-Leads, Body 10x10mm, Pitch 0.8mm, IPC Medium Density)
footprint SOT307-2_L (QFP, 44-Leads, Body 10x10mm, Pitch 0.8mm, IPC High Density)
footprint SOT307-2_M (QFP, 44-Leads, Body 10x10mm, Pitch 0.8mm, IPC Low Density)
pins: 1 P1.5/CEX2 (io), 2 P1.6/CEX3 (io), 3 P1.7/CEX4 (io), 4 RST (in), 5 P3.0/RxD (io), 6 NIC, 7 P3.1/TxD (io), 8 P3.2/~{INT}0 (io), 9 P3.3/~{INT}1 (io), 10 P3.4/T0 (io), 11 P3.5/T1 (io), 12 P3.6/~{WR} (io), 13 P3.7/~{RD} (io), 14 XTAL2 (out), 15 XTAL1 (in), 16 VSS (power), 17 NIC, 18 P2.0/A8 (io), 19 P2.1/A9 (io), 20 P2.2/A10 (io), 21 P2.3/A11 (io), 22 P2.4/A12 (io), 23 P2.5/A13 (io), 24 P2.6/A14 (io), 25 P2.7/A15 (io), 26 ~{PSEN} (out), 27 ALE/~{PROG} (io), 28 NIC, 29 ~{EA}/VPP (in), 30 P0.7/AD7 (io), 31 P0.6/AD6 (io), 32 P0.5/AD5 (io), 33 P0.4/AD4 (io), 34 P0.3/AD3 (io), 35 P0.2/AD2 (io), 36 P0.1/AD1 (io), 37 P0.0/AD0 (io), 38 VCC (power), 39 NIC, 40 P1.0/T2 (io), 41 P1.1/T2EX (io), 42 P1.2/ECI (io), 43 P1.3/CEX0 (io), 44 P1.4/CEX1 (io)

## P87C51RB+IN
designator U?
80C51 8-Bit Microcontroller Family: 512 B RAM, 16 kB OTP, 5V, Low Power, High Speed
footprint SOT129-1 (DIP, Plastic; 40 Leads; Row Spacing 15.24 mm; Pitch 2.54 mm)
pins: 1 P1.0/T2 (io), 2 P1.1/T2EX (io), 3 P1.2/ECI (io), 4 P1.3/CEX0 (io), 5 P1.4/CEX1 (io), 6 P1.5/CEX2 (io), 7 P1.6/CEX3 (io), 8 P1.7/CEX4 (io), 9 RST (in), 10 P3.0/RxD (io), 11 P3.1/TxD (io), 12 P3.2/~{INT}0 (io), 13 P3.3/~{INT}1 (io), 14 P3.4/T0 (io), 15 P3.5/T1 (io), 16 P3.6/~{WR} (io), 17 P3.7/~{RD} (io), 18 XTAL2 (out), 19 XTAL1 (in), 20 VSS (power), 21 P2.0/A8 (io), 22 P2.1/A9 (io), 23 P2.2/A10 (io), 24 P2.3/A11 (io), 25 P2.4/A12 (io), 26 P2.5/A13 (io), 27 P2.6/A14 (io), 28 P2.7/A15 (io), 29 ~{PSEN} (out), 30 ALE/~{PROG} (io), 31 ~{EA}/VPP (in), 32 P0.7/AD7 (io), 33 P0.6/AD6 (io), 34 P0.5/AD5 (io), 35 P0.4/AD4 (io), 36 P0.3/AD3 (io), 37 P0.2/AD2 (io), 38 P0.1/AD1 (io), 39 P0.0/AD0 (io), 40 VCC (power)

## P87C51RB+JA
designator U?
80C51 8-Bit Microcontroller Family: 512 B RAM, 16 kB OTP, 5V, Low Power, High Speed
footprint SOT187-2_N (Leaded Chip Carrier, 44-Leads, Body 16.6x16.6mm, Pitch 1.27mm, IPC Medium Density)
footprint SOT187-2_L (Leaded Chip Carrier, 44-Leads, Body 16.6x16.6mm, Pitch 1.27mm, IPC High Density)
footprint SOT187-2_M (Leaded Chip Carrier, 44-Leads, Body 16.6x16.6mm, Pitch 1.27mm, IPC Low Density)
pins: 1 NIC, 2 P1.0/T2 (io), 3 P1.1/T2EX (io), 4 P1.2/ECI (io), 5 P1.3/CEX0 (io), 6 P1.4/CEX1 (io), 7 P1.5/CEX2 (io), 8 P1.6/CEX3 (io), 9 P1.7/CEX4 (io), 10 RST (in), 11 P3.0/RxD (io), 12 NIC, 13 P3.1/TxD (io), 14 P3.2/~{INT}0 (io), 15 P3.3/~{INT}1 (io), 16 P3.4/T0 (io), 17 P3.5/T1 (io), 18 P3.6/~{WR} (io), 19 P3.7/~{RD} (io), 20 XTAL2 (out), 21 XTAL1 (in), 22 VSS (power), 23 NIC, 24 P2.0/A8 (io), 25 P2.1/A9 (io), 26 P2.2/A10 (io), 27 P2.3/A11 (io), 28 P2.4/A12 (io), 29 P2.5/A13 (io), 30 P2.6/A14 (io), 31 P2.7/A15 (io), 32 ~{PSEN} (out), 33 ALE/~{PROG} (io), 34 NIC, 35 ~{EA}/VPP (in), 36 P0.7/AD7 (io), 37 P0.6/AD6 (io), 38 P0.5/AD5 (io), 39 P0.4/AD4 (io), 40 P0.3/AD3 (io), 41 P0.2/AD2 (io), 42 P0.1/AD1 (io), 43 P0.0/AD0 (io), 44 VCC (power)

## P87C51RB+JB
designator U?
80C51 8-Bit Microcontroller Family: 512 B RAM, 16 kB OTP, 5V, Low Power, High Speed
footprint SOT307-2_N (QFP, 44-Leads, Body 10x10mm, Pitch 0.8mm, IPC Medium Density)
footprint SOT307-2_L (QFP, 44-Leads, Body 10x10mm, Pitch 0.8mm, IPC High Density)
footprint SOT307-2_M (QFP, 44-Leads, Body 10x10mm, Pitch 0.8mm, IPC Low Density)
pins: 1 P1.5/CEX2 (io), 2 P1.6/CEX3 (io), 3 P1.7/CEX4 (io), 4 RST (in), 5 P3.0/RxD (io), 6 NIC, 7 P3.1/TxD (io), 8 P3.2/~{INT}0 (io), 9 P3.3/~{INT}1 (io), 10 P3.4/T0 (io), 11 P3.5/T1 (io), 12 P3.6/~{WR} (io), 13 P3.7/~{RD} (io), 14 XTAL2 (out), 15 XTAL1 (in), 16 VSS (power), 17 NIC, 18 P2.0/A8 (io), 19 P2.1/A9 (io), 20 P2.2/A10 (io), 21 P2.3/A11 (io), 22 P2.4/A12 (io), 23 P2.5/A13 (io), 24 P2.6/A14 (io), 25 P2.7/A15 (io), 26 ~{PSEN} (out), 27 ALE/~{PROG} (io), 28 NIC, 29 ~{EA}/VPP (in), 30 P0.7/AD7 (io), 31 P0.6/AD6 (io), 32 P0.5/AD5 (io), 33 P0.4/AD4 (io), 34 P0.3/AD3 (io), 35 P0.2/AD2 (io), 36 P0.1/AD1 (io), 37 P0.0/AD0 (io), 38 VCC (power), 39 NIC, 40 P1.0/T2 (io), 41 P1.1/T2EX (io), 42 P1.2/ECI (io), 43 P1.3/CEX0 (io), 44 P1.4/CEX1 (io)

## P87C51RB+JN
designator U?
80C51 8-Bit Microcontroller Family: 512 B RAM, 16 kB OTP, 5V, Low Power, High Speed
footprint SOT129-1 (DIP, Plastic; 40 Leads; Row Spacing 15.24 mm; Pitch 2.54 mm)
pins: 1 P1.0/T2 (io), 2 P1.1/T2EX (io), 3 P1.2/ECI (io), 4 P1.3/CEX0 (io), 5 P1.4/CEX1 (io), 6 P1.5/CEX2 (io), 7 P1.6/CEX3 (io), 8 P1.7/CEX4 (io), 9 RST (in), 10 P3.0/RxD (io), 11 P3.1/TxD (io), 12 P3.2/~{INT}0 (io), 13 P3.3/~{INT}1 (io), 14 P3.4/T0 (io), 15 P3.5/T1 (io), 16 P3.6/~{WR} (io), 17 P3.7/~{RD} (io), 18 XTAL2 (out), 19 XTAL1 (in), 20 VSS (power), 21 P2.0/A8 (io), 22 P2.1/A9 (io), 23 P2.2/A10 (io), 24 P2.3/A11 (io), 25 P2.4/A12 (io), 26 P2.5/A13 (io), 27 P2.6/A14 (io), 28 P2.7/A15 (io), 29 ~{PSEN} (out), 30 ALE/~{PROG} (io), 31 ~{EA}/VPP (in), 32 P0.7/AD7 (io), 33 P0.6/AD6 (io), 34 P0.5/AD5 (io), 35 P0.4/AD4 (io), 36 P0.3/AD3 (io), 37 P0.2/AD2 (io), 38 P0.1/AD1 (io), 39 P0.0/AD0 (io), 40 VCC (power)

## P87C51RC2BA
designator U?
80C51 8-Bit Microcontroller Family: 32 kB OTP with 512 B RAM, 2.7 to 5.5 V, Low Power, High Speed
footprint SOT187-2_N (Leaded Chip Carrier, 44-Leads, Body 16.6x16.6mm, Pitch 1.27mm, IPC Medium Density)
footprint SOT187-2_L (Leaded Chip Carrier, 44-Leads, Body 16.6x16.6mm, Pitch 1.27mm, IPC High Density)
footprint SOT187-2_M (Leaded Chip Carrier, 44-Leads, Body 16.6x16.6mm, Pitch 1.27mm, IPC Low Density)
pins: 1 NIC, 2 P1.0/T2 (io), 3 P1.1/T2EX (io), 4 P1.2/ECI (io), 5 P1.3/CEX0 (io), 6 P1.4/CEX1 (io), 7 P1.5/CEX2 (io), 8 P1.6/CEX3 (io), 9 P1.7/CEX4 (io), 10 RST (in), 11 P3.0/RxD (io), 12 NIC, 13 P3.1/TxD (io), 14 P3.2/~{INT}0 (io), 15 P3.3/~{INT}1 (io), 16 P3.4/T0 (io), 17 P3.5/T1 (io), 18 P3.6/~{WR} (io), 19 P3.7/~{RD} (io), 20 XTAL2 (out), 21 XTAL1 (in), 22 VSS (power), 23 NIC, 24 P2.0/A8 (io), 25 P2.1/A9 (io), 26 P2.2/A10 (io), 27 P2.3/A11 (io), 28 P2.4/A12 (io), 29 P2.5/A13 (io), 30 P2.6/A14 (io), 31 P2.7/A15 (io), 32 ~{PSEN} (out), 33 ALE/~{PROG} (io), 34 NIC, 35 ~{EA}/VPP (in), 36 P0.7/AD7 (io), 37 P0.6/AD6 (io), 38 P0.5/AD5 (io), 39 P0.4/AD4 (io), 40 P0.3/AD3 (io), 41 P0.2/AD2 (io), 42 P0.1/AD1 (io), 43 P0.0/AD0 (io), 44 VCC (power)

## P87C51RC2BBD
designator U?
80C51 8-Bit Microcontroller Family: 32 kB OTP with 512 B RAM, 2.7 to 5.5 V, Low Power, High Speed
footprint SOT389-1_N (Thin QFP, 44-Leads, Body 10x10mm, Pitch 0.8mm, IPC Medium Density)
footprint SOT389-1_L (Thin QFP, 44-Leads, Body 10x10mm, Pitch 0.8mm, IPC High Density)
footprint SOT389-1_M (Thin QFP, 44-Leads, Body 10x10mm, Pitch 0.8mm, IPC Low Density)
pins: 1 P1.5/CEX2 (io), 2 P1.6/CEX3 (io), 3 P1.7/CEX4 (io), 4 RST (in), 5 P3.0/RxD (io), 6 NIC, 7 P3.1/TxD (io), 8 P3.2/~{INT}0 (io), 9 P3.3/~{INT}1 (io), 10 P3.4/T0 (io), 11 P3.5/T1 (io), 12 P3.6/~{WR} (io), 13 P3.7/~{RD} (io), 14 XTAL2 (out), 15 XTAL1 (in), 16 VSS (power), 17 NIC, 18 P2.0/A8 (io), 19 P2.1/A9 (io), 20 P2.2/A10 (io), 21 P2.3/A11 (io), 22 P2.4/A12 (io), 23 P2.5/A13 (io), 24 P2.6/A14 (io), 25 P2.7/A15 (io), 26 ~{PSEN} (out), 27 ALE/~{PROG} (io), 28 NIC, 29 ~{EA}/VPP (in), 30 P0.7/AD7 (io), 31 P0.6/AD6 (io), 32 P0.5/AD5 (io), 33 P0.4/AD4 (io), 34 P0.3/AD3 (io), 35 P0.2/AD2 (io), 36 P0.1/AD1 (io), 37 P0.0/AD0 (io), 38 VCC (power), 39 NIC, 40 P1.0/T2 (io), 41 P1.1/T2EX (io), 42 P1.2/ECI (io), 43 P1.3/CEX0 (io), 44 P1.4/CEX1 (io)

## P87C51RC2BN
designator U?
80C51 8-Bit Microcontroller Family: 32 kB OTP with 512 B RAM, 2.7 to 5.5 V, Low Power, High Speed
footprint SOT129-1 (DIP, Plastic; 40 Leads; Row Spacing 15.24 mm; Pitch 2.54 mm)
pins: 1 P1.0/T2 (io), 2 P1.1/T2EX (io), 3 P1.2/ECI (io), 4 P1.3/CEX0 (io), 5 P1.4/CEX1 (io), 6 P1.5/CEX2 (io), 7 P1.6/CEX3 (io), 8 P1.7/CEX4 (io), 9 RST (in), 10 P3.0/RxD (io), 11 P3.1/TxD (io), 12 P3.2/~{INT}0 (io), 13 P3.3/~{INT}1 (io), 14 P3.4/T0 (io), 15 P3.5/T1 (io), 16 P3.6/~{WR} (io), 17 P3.7/~{RD} (io), 18 XTAL2 (out), 19 XTAL1 (in), 20 VSS (power), 21 P2.0/A8 (io), 22 P2.1/A9 (io), 23 P2.2/A10 (io), 24 P2.3/A11 (io), 25 P2.4/A12 (io), 26 P2.5/A13 (io), 27 P2.6/A14 (io), 28 P2.7/A15 (io), 29 ~{PSEN} (out), 30 ALE/~{PROG} (io), 31 ~{EA}/VPP (in), 32 P0.7/AD7 (io), 33 P0.6/AD6 (io), 34 P0.5/AD5 (io), 35 P0.4/AD4 (io), 36 P0.3/AD3 (io), 37 P0.2/AD2 (io), 38 P0.1/AD1 (io), 39 P0.0/AD0 (io), 40 VCC (power)

## P87C51RC2FA
designator U?
80C51 8-Bit Microcontroller Family: 32 kB OTP with 512 B RAM, 2.7 to 5.5 V, Low Power, High Speed
footprint SOT187-2_N (Leaded Chip Carrier, 44-Leads, Body 16.6x16.6mm, Pitch 1.27mm, IPC Medium Density)
footprint SOT187-2_L (Leaded Chip Carrier, 44-Leads, Body 16.6x16.6mm, Pitch 1.27mm, IPC High Density)
footprint SOT187-2_M (Leaded Chip Carrier, 44-Leads, Body 16.6x16.6mm, Pitch 1.27mm, IPC Low Density)
pins: 1 NIC, 2 P1.0/T2 (io), 3 P1.1/T2EX (io), 4 P1.2/ECI (io), 5 P1.3/CEX0 (io), 6 P1.4/CEX1 (io), 7 P1.5/CEX2 (io), 8 P1.6/CEX3 (io), 9 P1.7/CEX4 (io), 10 RST (in), 11 P3.0/RxD (io), 12 NIC, 13 P3.1/TxD (io), 14 P3.2/~{INT}0 (io), 15 P3.3/~{INT}1 (io), 16 P3.4/T0 (io), 17 P3.5/T1 (io), 18 P3.6/~{WR} (io), 19 P3.7/~{RD} (io), 20 XTAL2 (out), 21 XTAL1 (in), 22 VSS (power), 23 NIC, 24 P2.0/A8 (io), 25 P2.1/A9 (io), 26 P2.2/A10 (io), 27 P2.3/A11 (io), 28 P2.4/A12 (io), 29 P2.5/A13 (io), 30 P2.6/A14 (io), 31 P2.7/A15 (io), 32 ~{PSEN} (out), 33 ALE/~{PROG} (io), 34 NIC, 35 ~{EA}/VPP (in), 36 P0.7/AD7 (io), 37 P0.6/AD6 (io), 38 P0.5/AD5 (io), 39 P0.4/AD4 (io), 40 P0.3/AD3 (io), 41 P0.2/AD2 (io), 42 P0.1/AD1 (io), 43 P0.0/AD0 (io), 44 VCC (power)

## P87C51RC2FN
designator U?
80C51 8-Bit Microcontroller Family: 32 kB OTP with 512 B RAM, 2.7 to 5.5 V, Low Power, High Speed
footprint SOT129-1 (DIP, Plastic; 40 Leads; Row Spacing 15.24 mm; Pitch 2.54 mm)
pins: 1 P1.0/T2 (io), 2 P1.1/T2EX (io), 3 P1.2/ECI (io), 4 P1.3/CEX0 (io), 5 P1.4/CEX1 (io), 6 P1.5/CEX2 (io), 7 P1.6/CEX3 (io), 8 P1.7/CEX4 (io), 9 RST (in), 10 P3.0/RxD (io), 11 P3.1/TxD (io), 12 P3.2/~{INT}0 (io), 13 P3.3/~{INT}1 (io), 14 P3.4/T0 (io), 15 P3.5/T1 (io), 16 P3.6/~{WR} (io), 17 P3.7/~{RD} (io), 18 XTAL2 (out), 19 XTAL1 (in), 20 VSS (power), 21 P2.0/A8 (io), 22 P2.1/A9 (io), 23 P2.2/A10 (io), 24 P2.3/A11 (io), 25 P2.4/A12 (io), 26 P2.5/A13 (io), 27 P2.6/A14 (io), 28 P2.7/A15 (io), 29 ~{PSEN} (out), 30 ALE/~{PROG} (io), 31 ~{EA}/VPP (in), 32 P0.7/AD7 (io), 33 P0.6/AD6 (io), 34 P0.5/AD5 (io), 35 P0.4/AD4 (io), 36 P0.3/AD3 (io), 37 P0.2/AD2 (io), 38 P0.1/AD1 (io), 39 P0.0/AD0 (io), 40 VCC (power)

## P87C51RC+4A
designator U?
80C51 8-Bit Microcontroller Family: 512 B RAM, 32 kB OTP, 2.7V-5.5V, Low Power, High Speed
footprint SOT187-2_N (Leaded Chip Carrier, 44-Leads, Body 16.6x16.6mm, Pitch 1.27mm, IPC Medium Density)
footprint SOT187-2_L (Leaded Chip Carrier, 44-Leads, Body 16.6x16.6mm, Pitch 1.27mm, IPC High Density)
footprint SOT187-2_M (Leaded Chip Carrier, 44-Leads, Body 16.6x16.6mm, Pitch 1.27mm, IPC Low Density)
pins: 1 NIC, 2 P1.0/T2 (io), 3 P1.1/T2EX (io), 4 P1.2/ECI (io), 5 P1.3/CEX0 (io), 6 P1.4/CEX1 (io), 7 P1.5/CEX2 (io), 8 P1.6/CEX3 (io), 9 P1.7/CEX4 (io), 10 RST (in), 11 P3.0/RxD (io), 12 NIC, 13 P3.1/TxD (io), 14 P3.2/~{INT}0 (io), 15 P3.3/~{INT}1 (io), 16 P3.4/T0 (io), 17 P3.5/T1 (io), 18 P3.6/~{WR} (io), 19 P3.7/~{RD} (io), 20 XTAL2 (out), 21 XTAL1 (in), 22 VSS (power), 23 NIC, 24 P2.0/A8 (io), 25 P2.1/A9 (io), 26 P2.2/A10 (io), 27 P2.3/A11 (io), 28 P2.4/A12 (io), 29 P2.5/A13 (io), 30 P2.6/A14 (io), 31 P2.7/A15 (io), 32 ~{PSEN} (out), 33 ALE/~{PROG} (io), 34 NIC, 35 ~{EA}/VPP (in), 36 P0.7/AD7 (io), 37 P0.6/AD6 (io), 38 P0.5/AD5 (io), 39 P0.4/AD4 (io), 40 P0.3/AD3 (io), 41 P0.2/AD2 (io), 42 P0.1/AD1 (io), 43 P0.0/AD0 (io), 44 VCC (power)

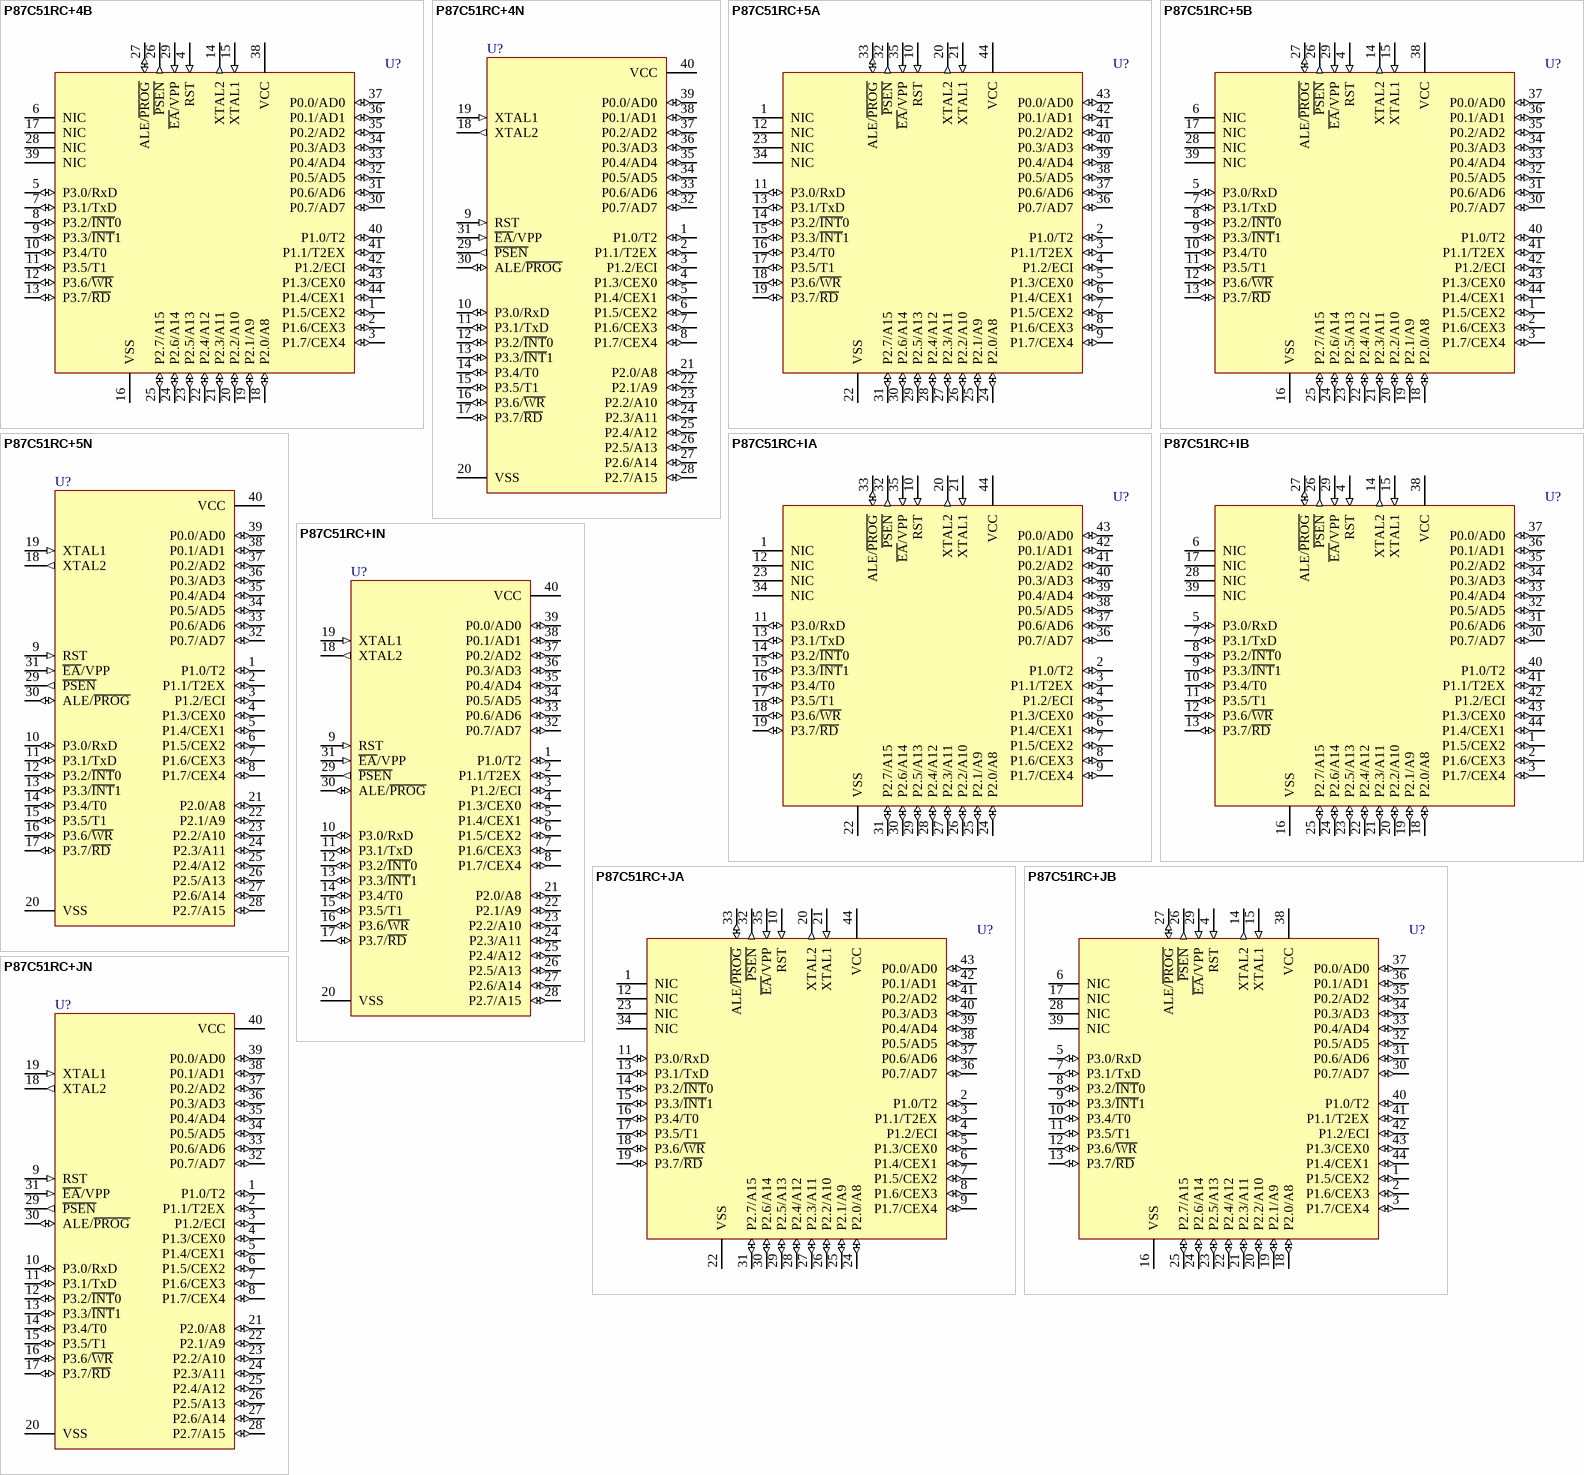
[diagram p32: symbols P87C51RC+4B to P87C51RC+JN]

## P87C51RC+4B
designator U?
80C51 8-Bit Microcontroller Family: 512 B RAM, 32 kB OTP, 2.7V-5.5V, Low Power, High Speed
footprint SOT307-2_N (QFP, 44-Leads, Body 10x10mm, Pitch 0.8mm, IPC Medium Density)
footprint SOT307-2_L (QFP, 44-Leads, Body 10x10mm, Pitch 0.8mm, IPC High Density)
footprint SOT307-2_M (QFP, 44-Leads, Body 10x10mm, Pitch 0.8mm, IPC Low Density)
pins: 1 P1.5/CEX2 (io), 2 P1.6/CEX3 (io), 3 P1.7/CEX4 (io), 4 RST (in), 5 P3.0/RxD (io), 6 NIC, 7 P3.1/TxD (io), 8 P3.2/~{INT}0 (io), 9 P3.3/~{INT}1 (io), 10 P3.4/T0 (io), 11 P3.5/T1 (io), 12 P3.6/~{WR} (io), 13 P3.7/~{RD} (io), 14 XTAL2 (out), 15 XTAL1 (in), 16 VSS (power), 17 NIC, 18 P2.0/A8 (io), 19 P2.1/A9 (io), 20 P2.2/A10 (io), 21 P2.3/A11 (io), 22 P2.4/A12 (io), 23 P2.5/A13 (io), 24 P2.6/A14 (io), 25 P2.7/A15 (io), 26 ~{PSEN} (out), 27 ALE/~{PROG} (io), 28 NIC, 29 ~{EA}/VPP (in), 30 P0.7/AD7 (io), 31 P0.6/AD6 (io), 32 P0.5/AD5 (io), 33 P0.4/AD4 (io), 34 P0.3/AD3 (io), 35 P0.2/AD2 (io), 36 P0.1/AD1 (io), 37 P0.0/AD0 (io), 38 VCC (power), 39 NIC, 40 P1.0/T2 (io), 41 P1.1/T2EX (io), 42 P1.2/ECI (io), 43 P1.3/CEX0 (io), 44 P1.4/CEX1 (io)

## P87C51RC+4N
designator U?
80C51 8-Bit Microcontroller Family: 512 B RAM, 32 kB OTP, 2.7V-5.5V, Low Power, High Speed
footprint SOT129-1 (DIP, Plastic; 40 Leads; Row Spacing 15.24 mm; Pitch 2.54 mm)
pins: 1 P1.0/T2 (io), 2 P1.1/T2EX (io), 3 P1.2/ECI (io), 4 P1.3/CEX0 (io), 5 P1.4/CEX1 (io), 6 P1.5/CEX2 (io), 7 P1.6/CEX3 (io), 8 P1.7/CEX4 (io), 9 RST (in), 10 P3.0/RxD (io), 11 P3.1/TxD (io), 12 P3.2/~{INT}0 (io), 13 P3.3/~{INT}1 (io), 14 P3.4/T0 (io), 15 P3.5/T1 (io), 16 P3.6/~{WR} (io), 17 P3.7/~{RD} (io), 18 XTAL2 (out), 19 XTAL1 (in), 20 VSS (power), 21 P2.0/A8 (io), 22 P2.1/A9 (io), 23 P2.2/A10 (io), 24 P2.3/A11 (io), 25 P2.4/A12 (io), 26 P2.5/A13 (io), 27 P2.6/A14 (io), 28 P2.7/A15 (io), 29 ~{PSEN} (out), 30 ALE/~{PROG} (io), 31 ~{EA}/VPP (in), 32 P0.7/AD7 (io), 33 P0.6/AD6 (io), 34 P0.5/AD5 (io), 35 P0.4/AD4 (io), 36 P0.3/AD3 (io), 37 P0.2/AD2 (io), 38 P0.1/AD1 (io), 39 P0.0/AD0 (io), 40 VCC (power)

## P87C51RC+5A
designator U?
80C51 8-Bit Microcontroller Family: 512 B RAM, 32 kB OTP, 2.7V-5.5V, Low Power, High Speed
footprint SOT187-2_N (Leaded Chip Carrier, 44-Leads, Body 16.6x16.6mm, Pitch 1.27mm, IPC Medium Density)
footprint SOT187-2_L (Leaded Chip Carrier, 44-Leads, Body 16.6x16.6mm, Pitch 1.27mm, IPC High Density)
footprint SOT187-2_M (Leaded Chip Carrier, 44-Leads, Body 16.6x16.6mm, Pitch 1.27mm, IPC Low Density)
pins: 1 NIC, 2 P1.0/T2 (io), 3 P1.1/T2EX (io), 4 P1.2/ECI (io), 5 P1.3/CEX0 (io), 6 P1.4/CEX1 (io), 7 P1.5/CEX2 (io), 8 P1.6/CEX3 (io), 9 P1.7/CEX4 (io), 10 RST (in), 11 P3.0/RxD (io), 12 NIC, 13 P3.1/TxD (io), 14 P3.2/~{INT}0 (io), 15 P3.3/~{INT}1 (io), 16 P3.4/T0 (io), 17 P3.5/T1 (io), 18 P3.6/~{WR} (io), 19 P3.7/~{RD} (io), 20 XTAL2 (out), 21 XTAL1 (in), 22 VSS (power), 23 NIC, 24 P2.0/A8 (io), 25 P2.1/A9 (io), 26 P2.2/A10 (io), 27 P2.3/A11 (io), 28 P2.4/A12 (io), 29 P2.5/A13 (io), 30 P2.6/A14 (io), 31 P2.7/A15 (io), 32 ~{PSEN} (out), 33 ALE/~{PROG} (io), 34 NIC, 35 ~{EA}/VPP (in), 36 P0.7/AD7 (io), 37 P0.6/AD6 (io), 38 P0.5/AD5 (io), 39 P0.4/AD4 (io), 40 P0.3/AD3 (io), 41 P0.2/AD2 (io), 42 P0.1/AD1 (io), 43 P0.0/AD0 (io), 44 VCC (power)

## P87C51RC+5B
designator U?
80C51 8-Bit Microcontroller Family: 512 B RAM, 32 kB OTP, 2.7V-5.5V, Low Power, High Speed
footprint SOT307-2_N (QFP, 44-Leads, Body 10x10mm, Pitch 0.8mm, IPC Medium Density)
footprint SOT307-2_L (QFP, 44-Leads, Body 10x10mm, Pitch 0.8mm, IPC High Density)
footprint SOT307-2_M (QFP, 44-Leads, Body 10x10mm, Pitch 0.8mm, IPC Low Density)
pins: 1 P1.5/CEX2 (io), 2 P1.6/CEX3 (io), 3 P1.7/CEX4 (io), 4 RST (in), 5 P3.0/RxD (io), 6 NIC, 7 P3.1/TxD (io), 8 P3.2/~{INT}0 (io), 9 P3.3/~{INT}1 (io), 10 P3.4/T0 (io), 11 P3.5/T1 (io), 12 P3.6/~{WR} (io), 13 P3.7/~{RD} (io), 14 XTAL2 (out), 15 XTAL1 (in), 16 VSS (power), 17 NIC, 18 P2.0/A8 (io), 19 P2.1/A9 (io), 20 P2.2/A10 (io), 21 P2.3/A11 (io), 22 P2.4/A12 (io), 23 P2.5/A13 (io), 24 P2.6/A14 (io), 25 P2.7/A15 (io), 26 ~{PSEN} (out), 27 ALE/~{PROG} (io), 28 NIC, 29 ~{EA}/VPP (in), 30 P0.7/AD7 (io), 31 P0.6/AD6 (io), 32 P0.5/AD5 (io), 33 P0.4/AD4 (io), 34 P0.3/AD3 (io), 35 P0.2/AD2 (io), 36 P0.1/AD1 (io), 37 P0.0/AD0 (io), 38 VCC (power), 39 NIC, 40 P1.0/T2 (io), 41 P1.1/T2EX (io), 42 P1.2/ECI (io), 43 P1.3/CEX0 (io), 44 P1.4/CEX1 (io)

## P87C51RC+5N
designator U?
80C51 8-Bit Microcontroller Family: 512 B RAM, 32 kB OTP, 2.7V-5.5V, Low Power, High Speed
footprint SOT129-1 (DIP, Plastic; 40 Leads; Row Spacing 15.24 mm; Pitch 2.54 mm)
pins: 1 P1.0/T2 (io), 2 P1.1/T2EX (io), 3 P1.2/ECI (io), 4 P1.3/CEX0 (io), 5 P1.4/CEX1 (io), 6 P1.5/CEX2 (io), 7 P1.6/CEX3 (io), 8 P1.7/CEX4 (io), 9 RST (in), 10 P3.0/RxD (io), 11 P3.1/TxD (io), 12 P3.2/~{INT}0 (io), 13 P3.3/~{INT}1 (io), 14 P3.4/T0 (io), 15 P3.5/T1 (io), 16 P3.6/~{WR} (io), 17 P3.7/~{RD} (io), 18 XTAL2 (out), 19 XTAL1 (in), 20 VSS (power), 21 P2.0/A8 (io), 22 P2.1/A9 (io), 23 P2.2/A10 (io), 24 P2.3/A11 (io), 25 P2.4/A12 (io), 26 P2.5/A13 (io), 27 P2.6/A14 (io), 28 P2.7/A15 (io), 29 ~{PSEN} (out), 30 ALE/~{PROG} (io), 31 ~{EA}/VPP (in), 32 P0.7/AD7 (io), 33 P0.6/AD6 (io), 34 P0.5/AD5 (io), 35 P0.4/AD4 (io), 36 P0.3/AD3 (io), 37 P0.2/AD2 (io), 38 P0.1/AD1 (io), 39 P0.0/AD0 (io), 40 VCC (power)

## P87C51RC+IA
designator U?
80C51 8-Bit Microcontroller Family: 512 B RAM, 32 kB OTP, 5V, Low Power, High Speed
footprint SOT187-2_N (Leaded Chip Carrier, 44-Leads, Body 16.6x16.6mm, Pitch 1.27mm, IPC Medium Density)
footprint SOT187-2_L (Leaded Chip Carrier, 44-Leads, Body 16.6x16.6mm, Pitch 1.27mm, IPC High Density)
footprint SOT187-2_M (Leaded Chip Carrier, 44-Leads, Body 16.6x16.6mm, Pitch 1.27mm, IPC Low Density)
pins: 1 NIC, 2 P1.0/T2 (io), 3 P1.1/T2EX (io), 4 P1.2/ECI (io), 5 P1.3/CEX0 (io), 6 P1.4/CEX1 (io), 7 P1.5/CEX2 (io), 8 P1.6/CEX3 (io), 9 P1.7/CEX4 (io), 10 RST (in), 11 P3.0/RxD (io), 12 NIC, 13 P3.1/TxD (io), 14 P3.2/~{INT}0 (io), 15 P3.3/~{INT}1 (io), 16 P3.4/T0 (io), 17 P3.5/T1 (io), 18 P3.6/~{WR} (io), 19 P3.7/~{RD} (io), 20 XTAL2 (out), 21 XTAL1 (in), 22 VSS (power), 23 NIC, 24 P2.0/A8 (io), 25 P2.1/A9 (io), 26 P2.2/A10 (io), 27 P2.3/A11 (io), 28 P2.4/A12 (io), 29 P2.5/A13 (io), 30 P2.6/A14 (io), 31 P2.7/A15 (io), 32 ~{PSEN} (out), 33 ALE/~{PROG} (io), 34 NIC, 35 ~{EA}/VPP (in), 36 P0.7/AD7 (io), 37 P0.6/AD6 (io), 38 P0.5/AD5 (io), 39 P0.4/AD4 (io), 40 P0.3/AD3 (io), 41 P0.2/AD2 (io), 42 P0.1/AD1 (io), 43 P0.0/AD0 (io), 44 VCC (power)

## P87C51RC+IB
designator U?
80C51 8-Bit Microcontroller Family: 512 B RAM, 32 kB OTP, 5V, Low Power, High Speed
footprint SOT307-2_N (QFP, 44-Leads, Body 10x10mm, Pitch 0.8mm, IPC Medium Density)
footprint SOT307-2_L (QFP, 44-Leads, Body 10x10mm, Pitch 0.8mm, IPC High Density)
footprint SOT307-2_M (QFP, 44-Leads, Body 10x10mm, Pitch 0.8mm, IPC Low Density)
pins: 1 P1.5/CEX2 (io), 2 P1.6/CEX3 (io), 3 P1.7/CEX4 (io), 4 RST (in), 5 P3.0/RxD (io), 6 NIC, 7 P3.1/TxD (io), 8 P3.2/~{INT}0 (io), 9 P3.3/~{INT}1 (io), 10 P3.4/T0 (io), 11 P3.5/T1 (io), 12 P3.6/~{WR} (io), 13 P3.7/~{RD} (io), 14 XTAL2 (out), 15 XTAL1 (in), 16 VSS (power), 17 NIC, 18 P2.0/A8 (io), 19 P2.1/A9 (io), 20 P2.2/A10 (io), 21 P2.3/A11 (io), 22 P2.4/A12 (io), 23 P2.5/A13 (io), 24 P2.6/A14 (io), 25 P2.7/A15 (io), 26 ~{PSEN} (out), 27 ALE/~{PROG} (io), 28 NIC, 29 ~{EA}/VPP (in), 30 P0.7/AD7 (io), 31 P0.6/AD6 (io), 32 P0.5/AD5 (io), 33 P0.4/AD4 (io), 34 P0.3/AD3 (io), 35 P0.2/AD2 (io), 36 P0.1/AD1 (io), 37 P0.0/AD0 (io), 38 VCC (power), 39 NIC, 40 P1.0/T2 (io), 41 P1.1/T2EX (io), 42 P1.2/ECI (io), 43 P1.3/CEX0 (io), 44 P1.4/CEX1 (io)

## P87C51RC+IN
designator U?
80C51 8-Bit Microcontroller Family: 512 B RAM, 32 kB OTP, 5V, Low Power, High Speed
footprint SOT129-1 (DIP, Plastic; 40 Leads; Row Spacing 15.24 mm; Pitch 2.54 mm)
pins: 1 P1.0/T2 (io), 2 P1.1/T2EX (io), 3 P1.2/ECI (io), 4 P1.3/CEX0 (io), 5 P1.4/CEX1 (io), 6 P1.5/CEX2 (io), 7 P1.6/CEX3 (io), 8 P1.7/CEX4 (io), 9 RST (in), 10 P3.0/RxD (io), 11 P3.1/TxD (io), 12 P3.2/~{INT}0 (io), 13 P3.3/~{INT}1 (io), 14 P3.4/T0 (io), 15 P3.5/T1 (io), 16 P3.6/~{WR} (io), 17 P3.7/~{RD} (io), 18 XTAL2 (out), 19 XTAL1 (in), 20 VSS (power), 21 P2.0/A8 (io), 22 P2.1/A9 (io), 23 P2.2/A10 (io), 24 P2.3/A11 (io), 25 P2.4/A12 (io), 26 P2.5/A13 (io), 27 P2.6/A14 (io), 28 P2.7/A15 (io), 29 ~{PSEN} (out), 30 ALE/~{PROG} (io), 31 ~{EA}/VPP (in), 32 P0.7/AD7 (io), 33 P0.6/AD6 (io), 34 P0.5/AD5 (io), 35 P0.4/AD4 (io), 36 P0.3/AD3 (io), 37 P0.2/AD2 (io), 38 P0.1/AD1 (io), 39 P0.0/AD0 (io), 40 VCC (power)

## P87C51RC+JA
designator U?
80C51 8-Bit Microcontroller Family: 512 B RAM, 32 kB OTP, 5V, Low Power, High Speed
footprint SOT187-2_N (Leaded Chip Carrier, 44-Leads, Body 16.6x16.6mm, Pitch 1.27mm, IPC Medium Density)
footprint SOT187-2_L (Leaded Chip Carrier, 44-Leads, Body 16.6x16.6mm, Pitch 1.27mm, IPC High Density)
footprint SOT187-2_M (Leaded Chip Carrier, 44-Leads, Body 16.6x16.6mm, Pitch 1.27mm, IPC Low Density)
pins: 1 NIC, 2 P1.0/T2 (io), 3 P1.1/T2EX (io), 4 P1.2/ECI (io), 5 P1.3/CEX0 (io), 6 P1.4/CEX1 (io), 7 P1.5/CEX2 (io), 8 P1.6/CEX3 (io), 9 P1.7/CEX4 (io), 10 RST (in), 11 P3.0/RxD (io), 12 NIC, 13 P3.1/TxD (io), 14 P3.2/~{INT}0 (io), 15 P3.3/~{INT}1 (io), 16 P3.4/T0 (io), 17 P3.5/T1 (io), 18 P3.6/~{WR} (io), 19 P3.7/~{RD} (io), 20 XTAL2 (out), 21 XTAL1 (in), 22 VSS (power), 23 NIC, 24 P2.0/A8 (io), 25 P2.1/A9 (io), 26 P2.2/A10 (io), 27 P2.3/A11 (io), 28 P2.4/A12 (io), 29 P2.5/A13 (io), 30 P2.6/A14 (io), 31 P2.7/A15 (io), 32 ~{PSEN} (out), 33 ALE/~{PROG} (io), 34 NIC, 35 ~{EA}/VPP (in), 36 P0.7/AD7 (io), 37 P0.6/AD6 (io), 38 P0.5/AD5 (io), 39 P0.4/AD4 (io), 40 P0.3/AD3 (io), 41 P0.2/AD2 (io), 42 P0.1/AD1 (io), 43 P0.0/AD0 (io), 44 VCC (power)

## P87C51RC+JB
designator U?
80C51 8-Bit Microcontroller Family: 512 B RAM, 32 kB OTP, 5V, Low Power, High Speed
footprint SOT307-2_N (QFP, 44-Leads, Body 10x10mm, Pitch 0.8mm, IPC Medium Density)
footprint SOT307-2_L (QFP, 44-Leads, Body 10x10mm, Pitch 0.8mm, IPC High Density)
footprint SOT307-2_M (QFP, 44-Leads, Body 10x10mm, Pitch 0.8mm, IPC Low Density)
pins: 1 P1.5/CEX2 (io), 2 P1.6/CEX3 (io), 3 P1.7/CEX4 (io), 4 RST (in), 5 P3.0/RxD (io), 6 NIC, 7 P3.1/TxD (io), 8 P3.2/~{INT}0 (io), 9 P3.3/~{INT}1 (io), 10 P3.4/T0 (io), 11 P3.5/T1 (io), 12 P3.6/~{WR} (io), 13 P3.7/~{RD} (io), 14 XTAL2 (out), 15 XTAL1 (in), 16 VSS (power), 17 NIC, 18 P2.0/A8 (io), 19 P2.1/A9 (io), 20 P2.2/A10 (io), 21 P2.3/A11 (io), 22 P2.4/A12 (io), 23 P2.5/A13 (io), 24 P2.6/A14 (io), 25 P2.7/A15 (io), 26 ~{PSEN} (out), 27 ALE/~{PROG} (io), 28 NIC, 29 ~{EA}/VPP (in), 30 P0.7/AD7 (io), 31 P0.6/AD6 (io), 32 P0.5/AD5 (io), 33 P0.4/AD4 (io), 34 P0.3/AD3 (io), 35 P0.2/AD2 (io), 36 P0.1/AD1 (io), 37 P0.0/AD0 (io), 38 VCC (power), 39 NIC, 40 P1.0/T2 (io), 41 P1.1/T2EX (io), 42 P1.2/ECI (io), 43 P1.3/CEX0 (io), 44 P1.4/CEX1 (io)

## P87C51RC+JN
designator U?
80C51 8-Bit Microcontroller Family: 512 B RAM, 32 kB OTP, 5V, Low Power, High Speed
footprint SOT129-1 (DIP, Plastic; 40 Leads; Row Spacing 15.24 mm; Pitch 2.54 mm)
pins: 1 P1.0/T2 (io), 2 P1.1/T2EX (io), 3 P1.2/ECI (io), 4 P1.3/CEX0 (io), 5 P1.4/CEX1 (io), 6 P1.5/CEX2 (io), 7 P1.6/CEX3 (io), 8 P1.7/CEX4 (io), 9 RST (in), 10 P3.0/RxD (io), 11 P3.1/TxD (io), 12 P3.2/~{INT}0 (io), 13 P3.3/~{INT}1 (io), 14 P3.4/T0 (io), 15 P3.5/T1 (io), 16 P3.6/~{WR} (io), 17 P3.7/~{RD} (io), 18 XTAL2 (out), 19 XTAL1 (in), 20 VSS (power), 21 P2.0/A8 (io), 22 P2.1/A9 (io), 23 P2.2/A10 (io), 24 P2.3/A11 (io), 25 P2.4/A12 (io), 26 P2.5/A13 (io), 27 P2.6/A14 (io), 28 P2.7/A15 (io), 29 ~{PSEN} (out), 30 ALE/~{PROG} (io), 31 ~{EA}/VPP (in), 32 P0.7/AD7 (io), 33 P0.6/AD6 (io), 34 P0.5/AD5 (io), 35 P0.4/AD4 (io), 36 P0.3/AD3 (io), 37 P0.2/AD2 (io), 38 P0.1/AD1 (io), 39 P0.0/AD0 (io), 40 VCC (power)

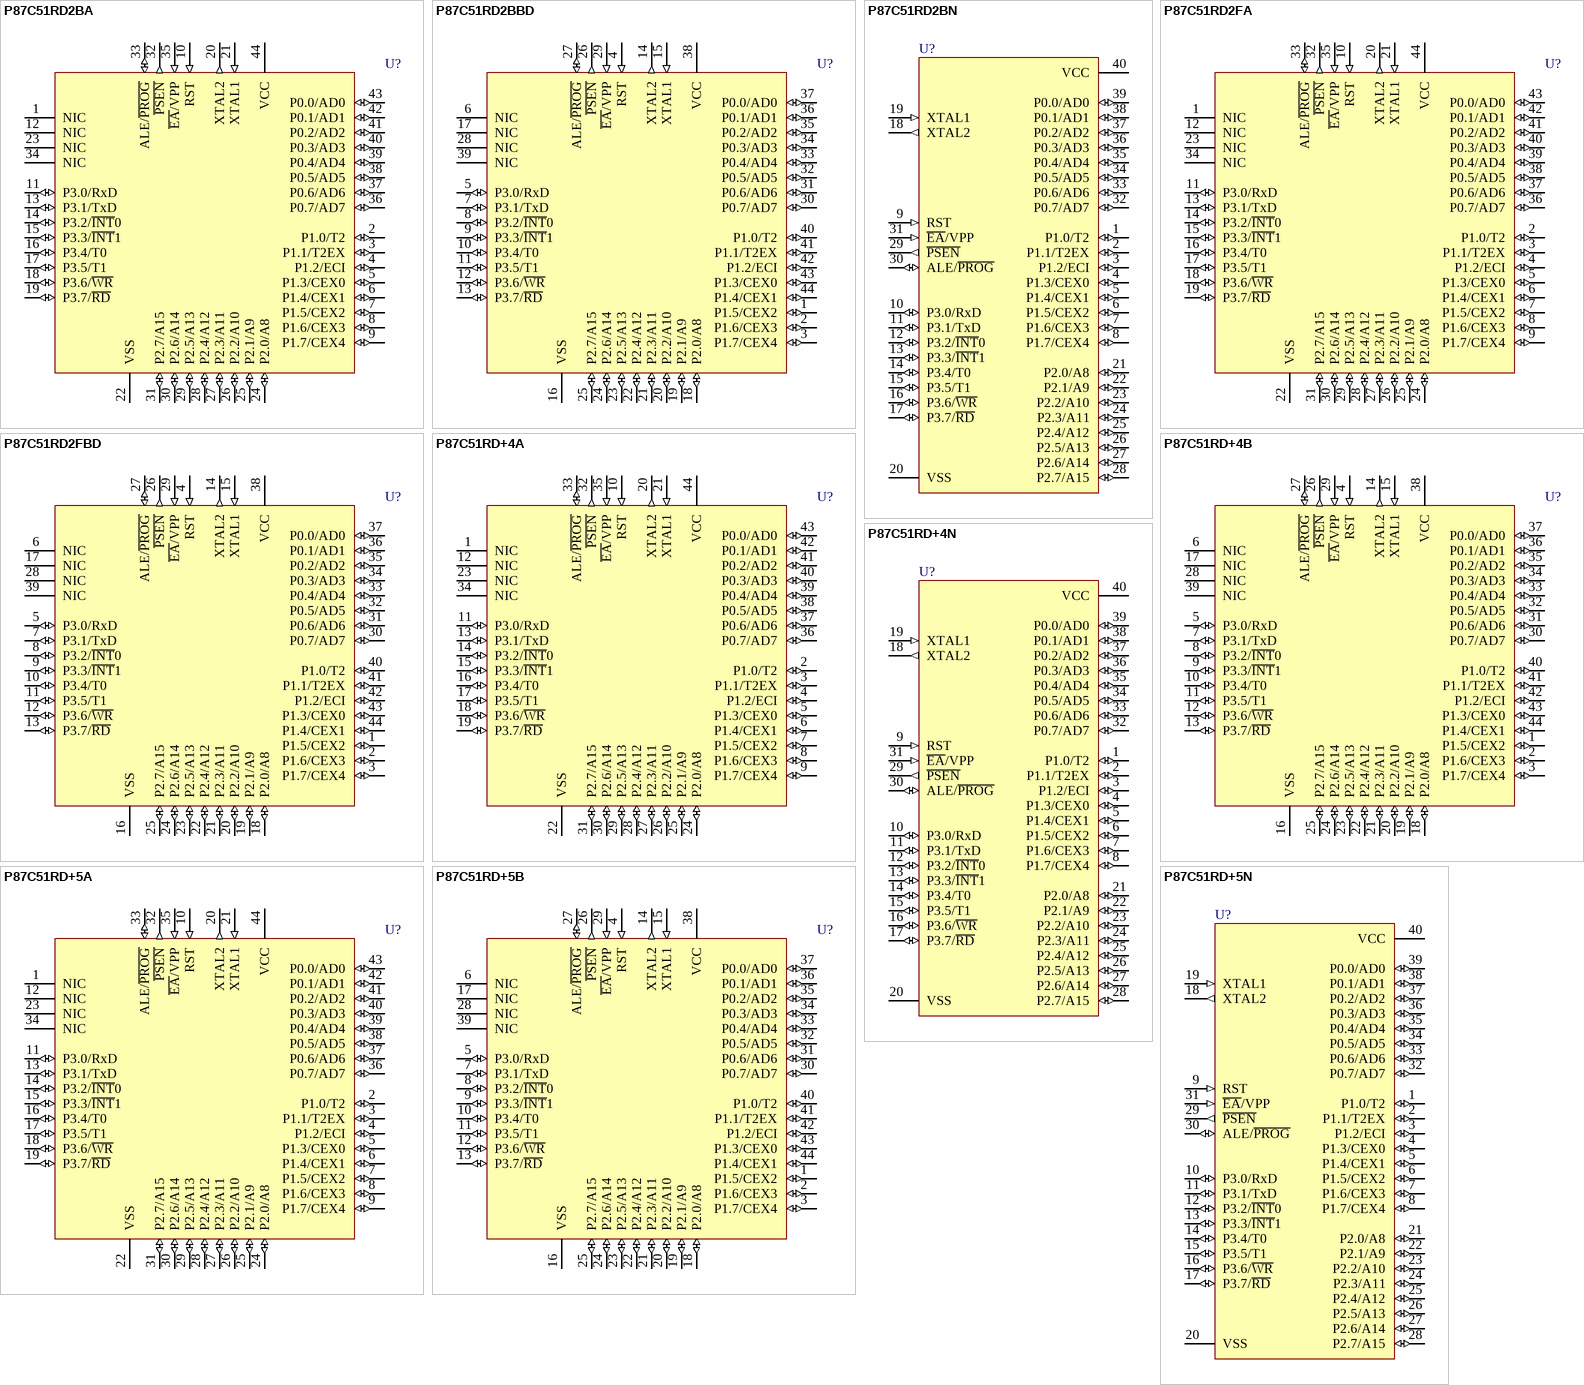
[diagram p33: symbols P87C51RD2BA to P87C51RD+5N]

## P87C51RD2BA
designator U?
80C51 8-Bit Microcontroller Family: 64 kB OTP with 1 kB RAM, 2.7 to 5.5 V, Low Power, High Speed
footprint SOT187-2_N (Leaded Chip Carrier, 44-Leads, Body 16.6x16.6mm, Pitch 1.27mm, IPC Medium Density)
footprint SOT187-2_L (Leaded Chip Carrier, 44-Leads, Body 16.6x16.6mm, Pitch 1.27mm, IPC High Density)
footprint SOT187-2_M (Leaded Chip Carrier, 44-Leads, Body 16.6x16.6mm, Pitch 1.27mm, IPC Low Density)
pins: 1 NIC, 2 P1.0/T2 (io), 3 P1.1/T2EX (io), 4 P1.2/ECI (io), 5 P1.3/CEX0 (io), 6 P1.4/CEX1 (io), 7 P1.5/CEX2 (io), 8 P1.6/CEX3 (io), 9 P1.7/CEX4 (io), 10 RST (in), 11 P3.0/RxD (io), 12 NIC, 13 P3.1/TxD (io), 14 P3.2/~{INT}0 (io), 15 P3.3/~{INT}1 (io), 16 P3.4/T0 (io), 17 P3.5/T1 (io), 18 P3.6/~{WR} (io), 19 P3.7/~{RD} (io), 20 XTAL2 (out), 21 XTAL1 (in), 22 VSS (power), 23 NIC, 24 P2.0/A8 (io), 25 P2.1/A9 (io), 26 P2.2/A10 (io), 27 P2.3/A11 (io), 28 P2.4/A12 (io), 29 P2.5/A13 (io), 30 P2.6/A14 (io), 31 P2.7/A15 (io), 32 ~{PSEN} (out), 33 ALE/~{PROG} (io), 34 NIC, 35 ~{EA}/VPP (in), 36 P0.7/AD7 (io), 37 P0.6/AD6 (io), 38 P0.5/AD5 (io), 39 P0.4/AD4 (io), 40 P0.3/AD3 (io), 41 P0.2/AD2 (io), 42 P0.1/AD1 (io), 43 P0.0/AD0 (io), 44 VCC (power)

## P87C51RD2BBD
designator U?
80C51 8-Bit Microcontroller Family: 64 kB OTP with 1 kB RAM, 2.7 to 5.5 V, Low Power, High Speed
footprint SOT389-1_N (Thin QFP, 44-Leads, Body 10x10mm, Pitch 0.8mm, IPC Medium Density)
footprint SOT389-1_L (Thin QFP, 44-Leads, Body 10x10mm, Pitch 0.8mm, IPC High Density)
footprint SOT389-1_M (Thin QFP, 44-Leads, Body 10x10mm, Pitch 0.8mm, IPC Low Density)
pins: 1 P1.5/CEX2 (io), 2 P1.6/CEX3 (io), 3 P1.7/CEX4 (io), 4 RST (in), 5 P3.0/RxD (io), 6 NIC, 7 P3.1/TxD (io), 8 P3.2/~{INT}0 (io), 9 P3.3/~{INT}1 (io), 10 P3.4/T0 (io), 11 P3.5/T1 (io), 12 P3.6/~{WR} (io), 13 P3.7/~{RD} (io), 14 XTAL2 (out), 15 XTAL1 (in), 16 VSS (power), 17 NIC, 18 P2.0/A8 (io), 19 P2.1/A9 (io), 20 P2.2/A10 (io), 21 P2.3/A11 (io), 22 P2.4/A12 (io), 23 P2.5/A13 (io), 24 P2.6/A14 (io), 25 P2.7/A15 (io), 26 ~{PSEN} (out), 27 ALE/~{PROG} (io), 28 NIC, 29 ~{EA}/VPP (in), 30 P0.7/AD7 (io), 31 P0.6/AD6 (io), 32 P0.5/AD5 (io), 33 P0.4/AD4 (io), 34 P0.3/AD3 (io), 35 P0.2/AD2 (io), 36 P0.1/AD1 (io), 37 P0.0/AD0 (io), 38 VCC (power), 39 NIC, 40 P1.0/T2 (io), 41 P1.1/T2EX (io), 42 P1.2/ECI (io), 43 P1.3/CEX0 (io), 44 P1.4/CEX1 (io)

## P87C51RD2BN
designator U?
80C51 8-Bit Microcontroller Family: 64 kB OTP with 1 kB RAM, 2.7 to 5.5 V, Low Power, High Speed
footprint SOT129-1 (DIP, Plastic; 40 Leads; Row Spacing 15.24 mm; Pitch 2.54 mm)
pins: 1 P1.0/T2 (io), 2 P1.1/T2EX (io), 3 P1.2/ECI (io), 4 P1.3/CEX0 (io), 5 P1.4/CEX1 (io), 6 P1.5/CEX2 (io), 7 P1.6/CEX3 (io), 8 P1.7/CEX4 (io), 9 RST (in), 10 P3.0/RxD (io), 11 P3.1/TxD (io), 12 P3.2/~{INT}0 (io), 13 P3.3/~{INT}1 (io), 14 P3.4/T0 (io), 15 P3.5/T1 (io), 16 P3.6/~{WR} (io), 17 P3.7/~{RD} (io), 18 XTAL2 (out), 19 XTAL1 (in), 20 VSS (power), 21 P2.0/A8 (io), 22 P2.1/A9 (io), 23 P2.2/A10 (io), 24 P2.3/A11 (io), 25 P2.4/A12 (io), 26 P2.5/A13 (io), 27 P2.6/A14 (io), 28 P2.7/A15 (io), 29 ~{PSEN} (out), 30 ALE/~{PROG} (io), 31 ~{EA}/VPP (in), 32 P0.7/AD7 (io), 33 P0.6/AD6 (io), 34 P0.5/AD5 (io), 35 P0.4/AD4 (io), 36 P0.3/AD3 (io), 37 P0.2/AD2 (io), 38 P0.1/AD1 (io), 39 P0.0/AD0 (io), 40 VCC (power)

## P87C51RD2FA
designator U?
80C51 8-Bit Microcontroller Family: 64 kB OTP with 1 kB RAM, 2.7 to 5.5 V, Low Power, High Speed
footprint SOT187-2_N (Leaded Chip Carrier, 44-Leads, Body 16.6x16.6mm, Pitch 1.27mm, IPC Medium Density)
footprint SOT187-2_L (Leaded Chip Carrier, 44-Leads, Body 16.6x16.6mm, Pitch 1.27mm, IPC High Density)
footprint SOT187-2_M (Leaded Chip Carrier, 44-Leads, Body 16.6x16.6mm, Pitch 1.27mm, IPC Low Density)
pins: 1 NIC, 2 P1.0/T2 (io), 3 P1.1/T2EX (io), 4 P1.2/ECI (io), 5 P1.3/CEX0 (io), 6 P1.4/CEX1 (io), 7 P1.5/CEX2 (io), 8 P1.6/CEX3 (io), 9 P1.7/CEX4 (io), 10 RST (in), 11 P3.0/RxD (io), 12 NIC, 13 P3.1/TxD (io), 14 P3.2/~{INT}0 (io), 15 P3.3/~{INT}1 (io), 16 P3.4/T0 (io), 17 P3.5/T1 (io), 18 P3.6/~{WR} (io), 19 P3.7/~{RD} (io), 20 XTAL2 (out), 21 XTAL1 (in), 22 VSS (power), 23 NIC, 24 P2.0/A8 (io), 25 P2.1/A9 (io), 26 P2.2/A10 (io), 27 P2.3/A11 (io), 28 P2.4/A12 (io), 29 P2.5/A13 (io), 30 P2.6/A14 (io), 31 P2.7/A15 (io), 32 ~{PSEN} (out), 33 ALE/~{PROG} (io), 34 NIC, 35 ~{EA}/VPP (in), 36 P0.7/AD7 (io), 37 P0.6/AD6 (io), 38 P0.5/AD5 (io), 39 P0.4/AD4 (io), 40 P0.3/AD3 (io), 41 P0.2/AD2 (io), 42 P0.1/AD1 (io), 43 P0.0/AD0 (io), 44 VCC (power)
